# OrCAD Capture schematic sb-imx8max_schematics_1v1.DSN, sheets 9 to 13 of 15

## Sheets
9 02. B2B CONNECTOR: size C; title: 02. B2B CONNECTOR; note: 8000064001
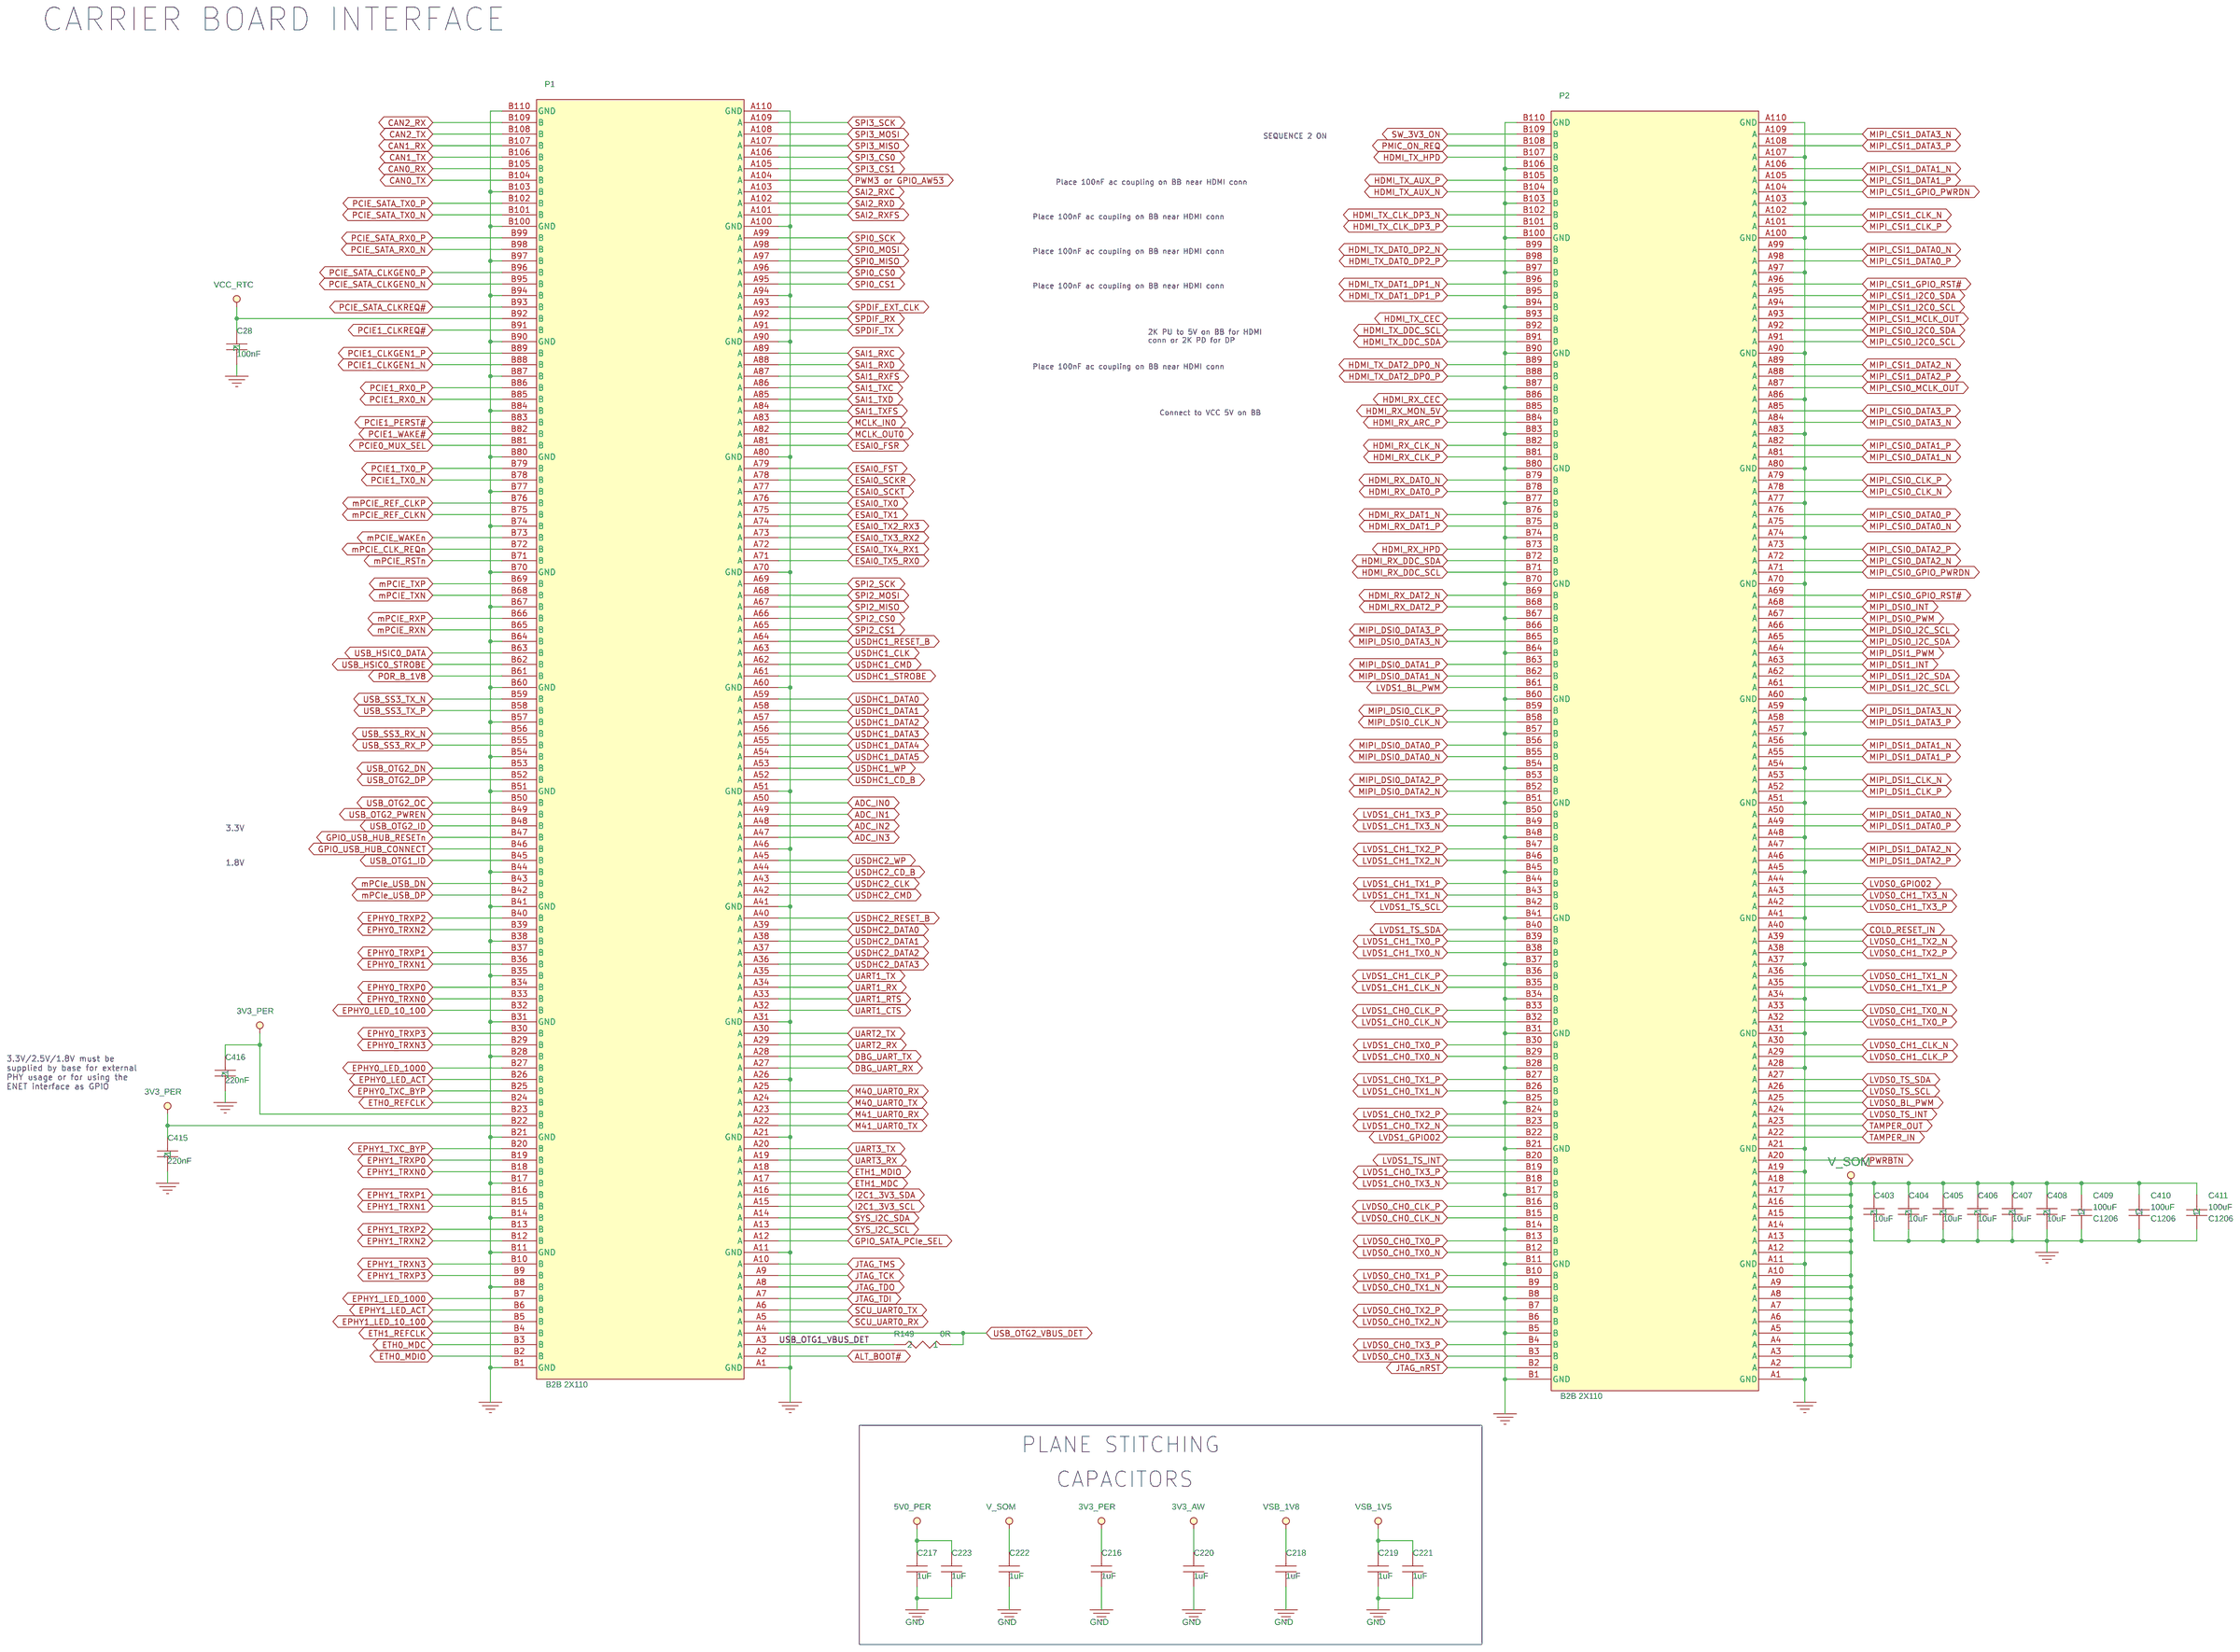
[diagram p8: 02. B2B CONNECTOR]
10 03. ETHERNET 0 , 1: size B; title: 03. ETHERNET 1 , 2; note: 8000064001
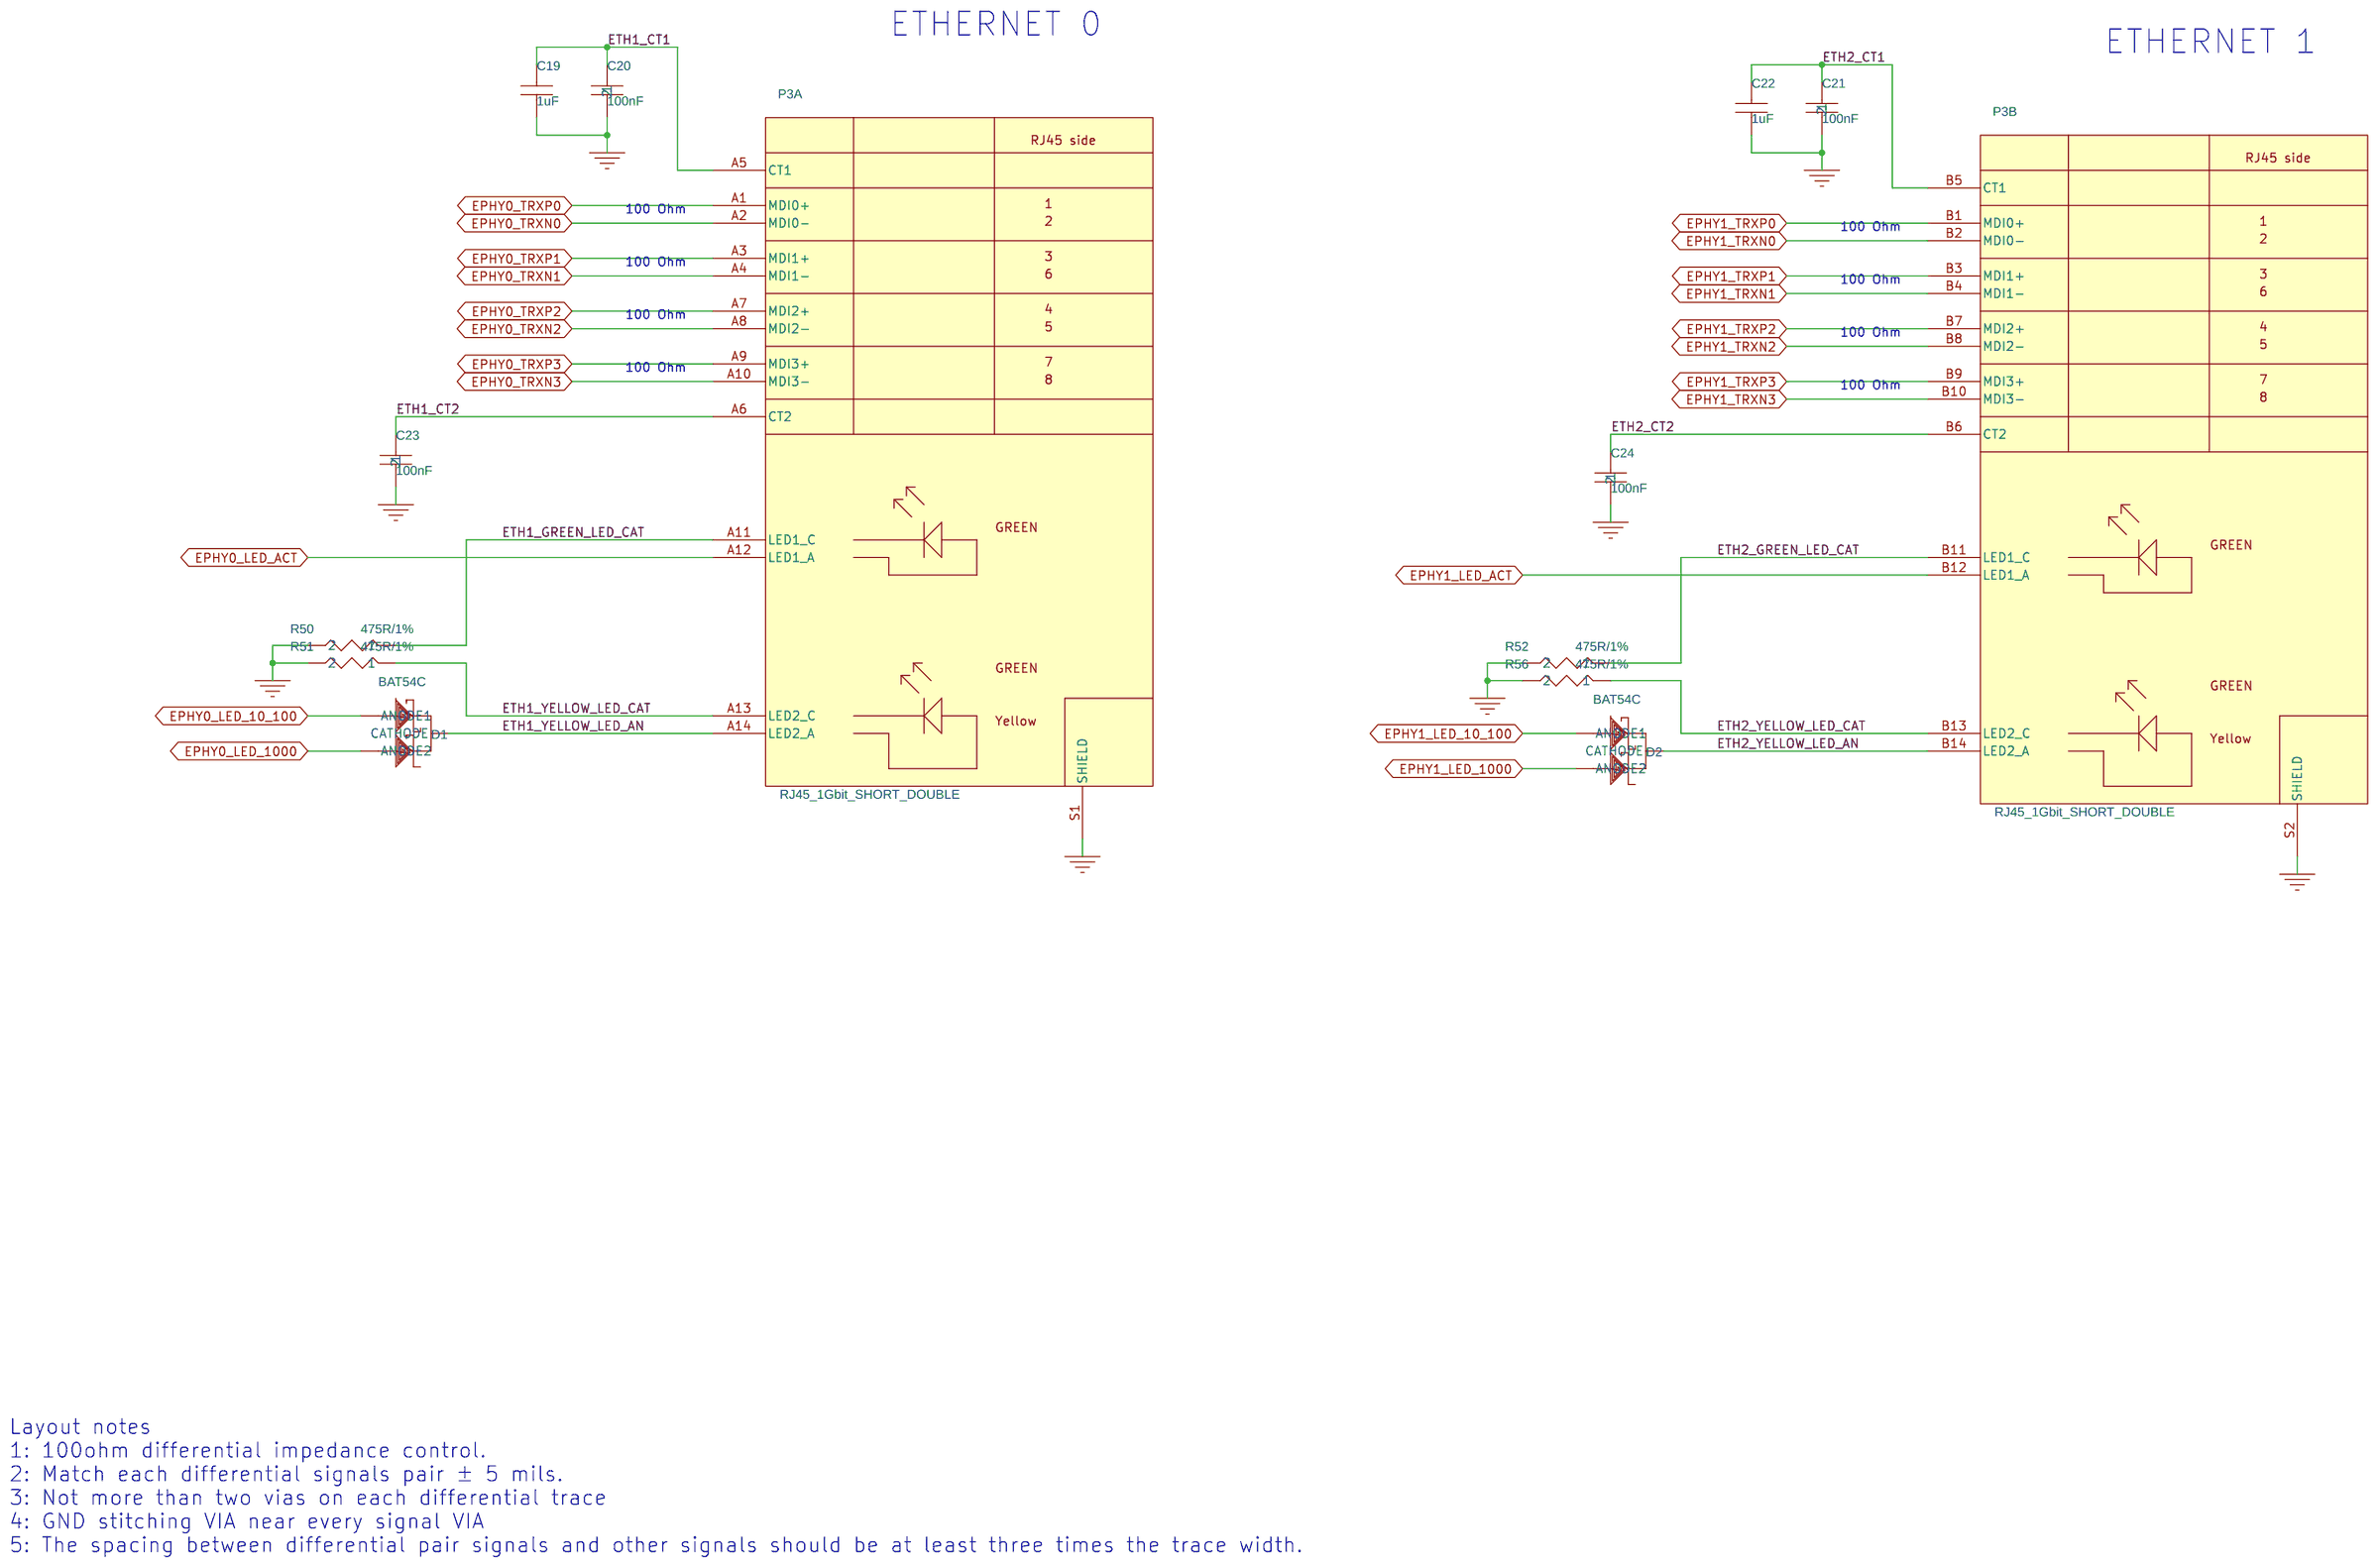
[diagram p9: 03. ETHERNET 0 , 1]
11 04. USB: size C; title: 04. USB; note: 8010055003
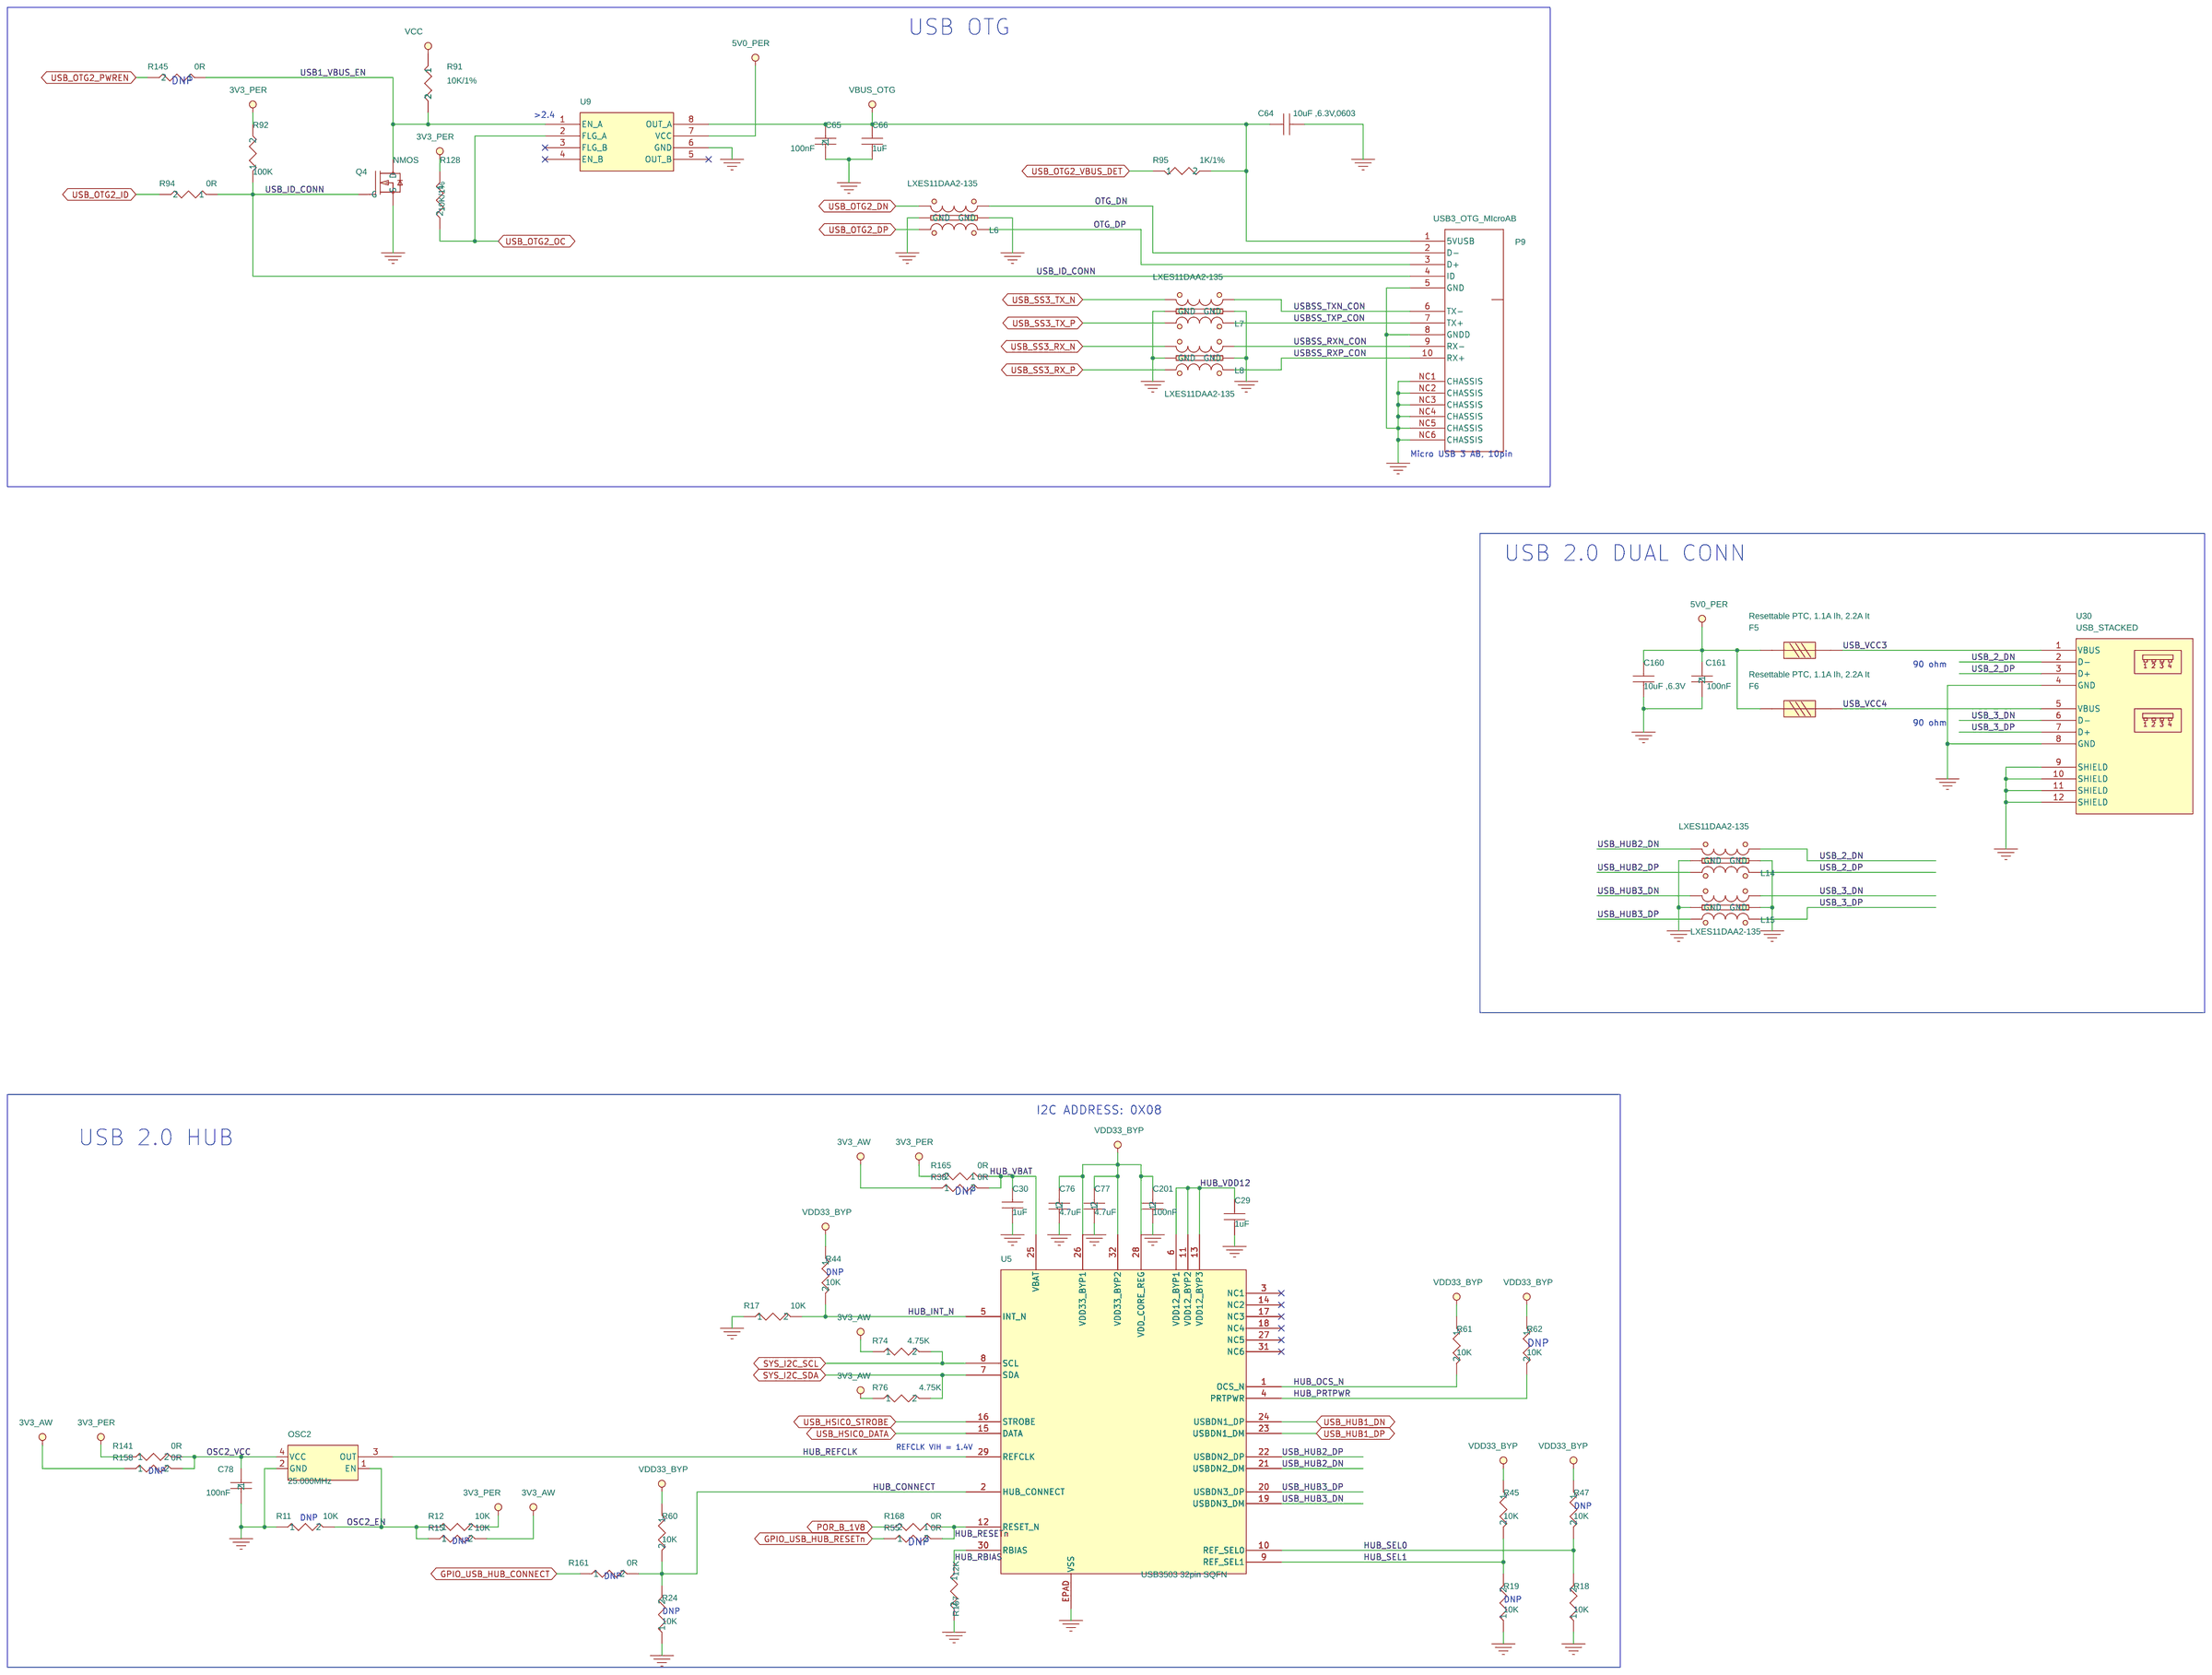
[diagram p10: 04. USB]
12 06. JTAG, 100 MIL CONN: size B; title: 06. 100 MIL CONN; note: 8010055003
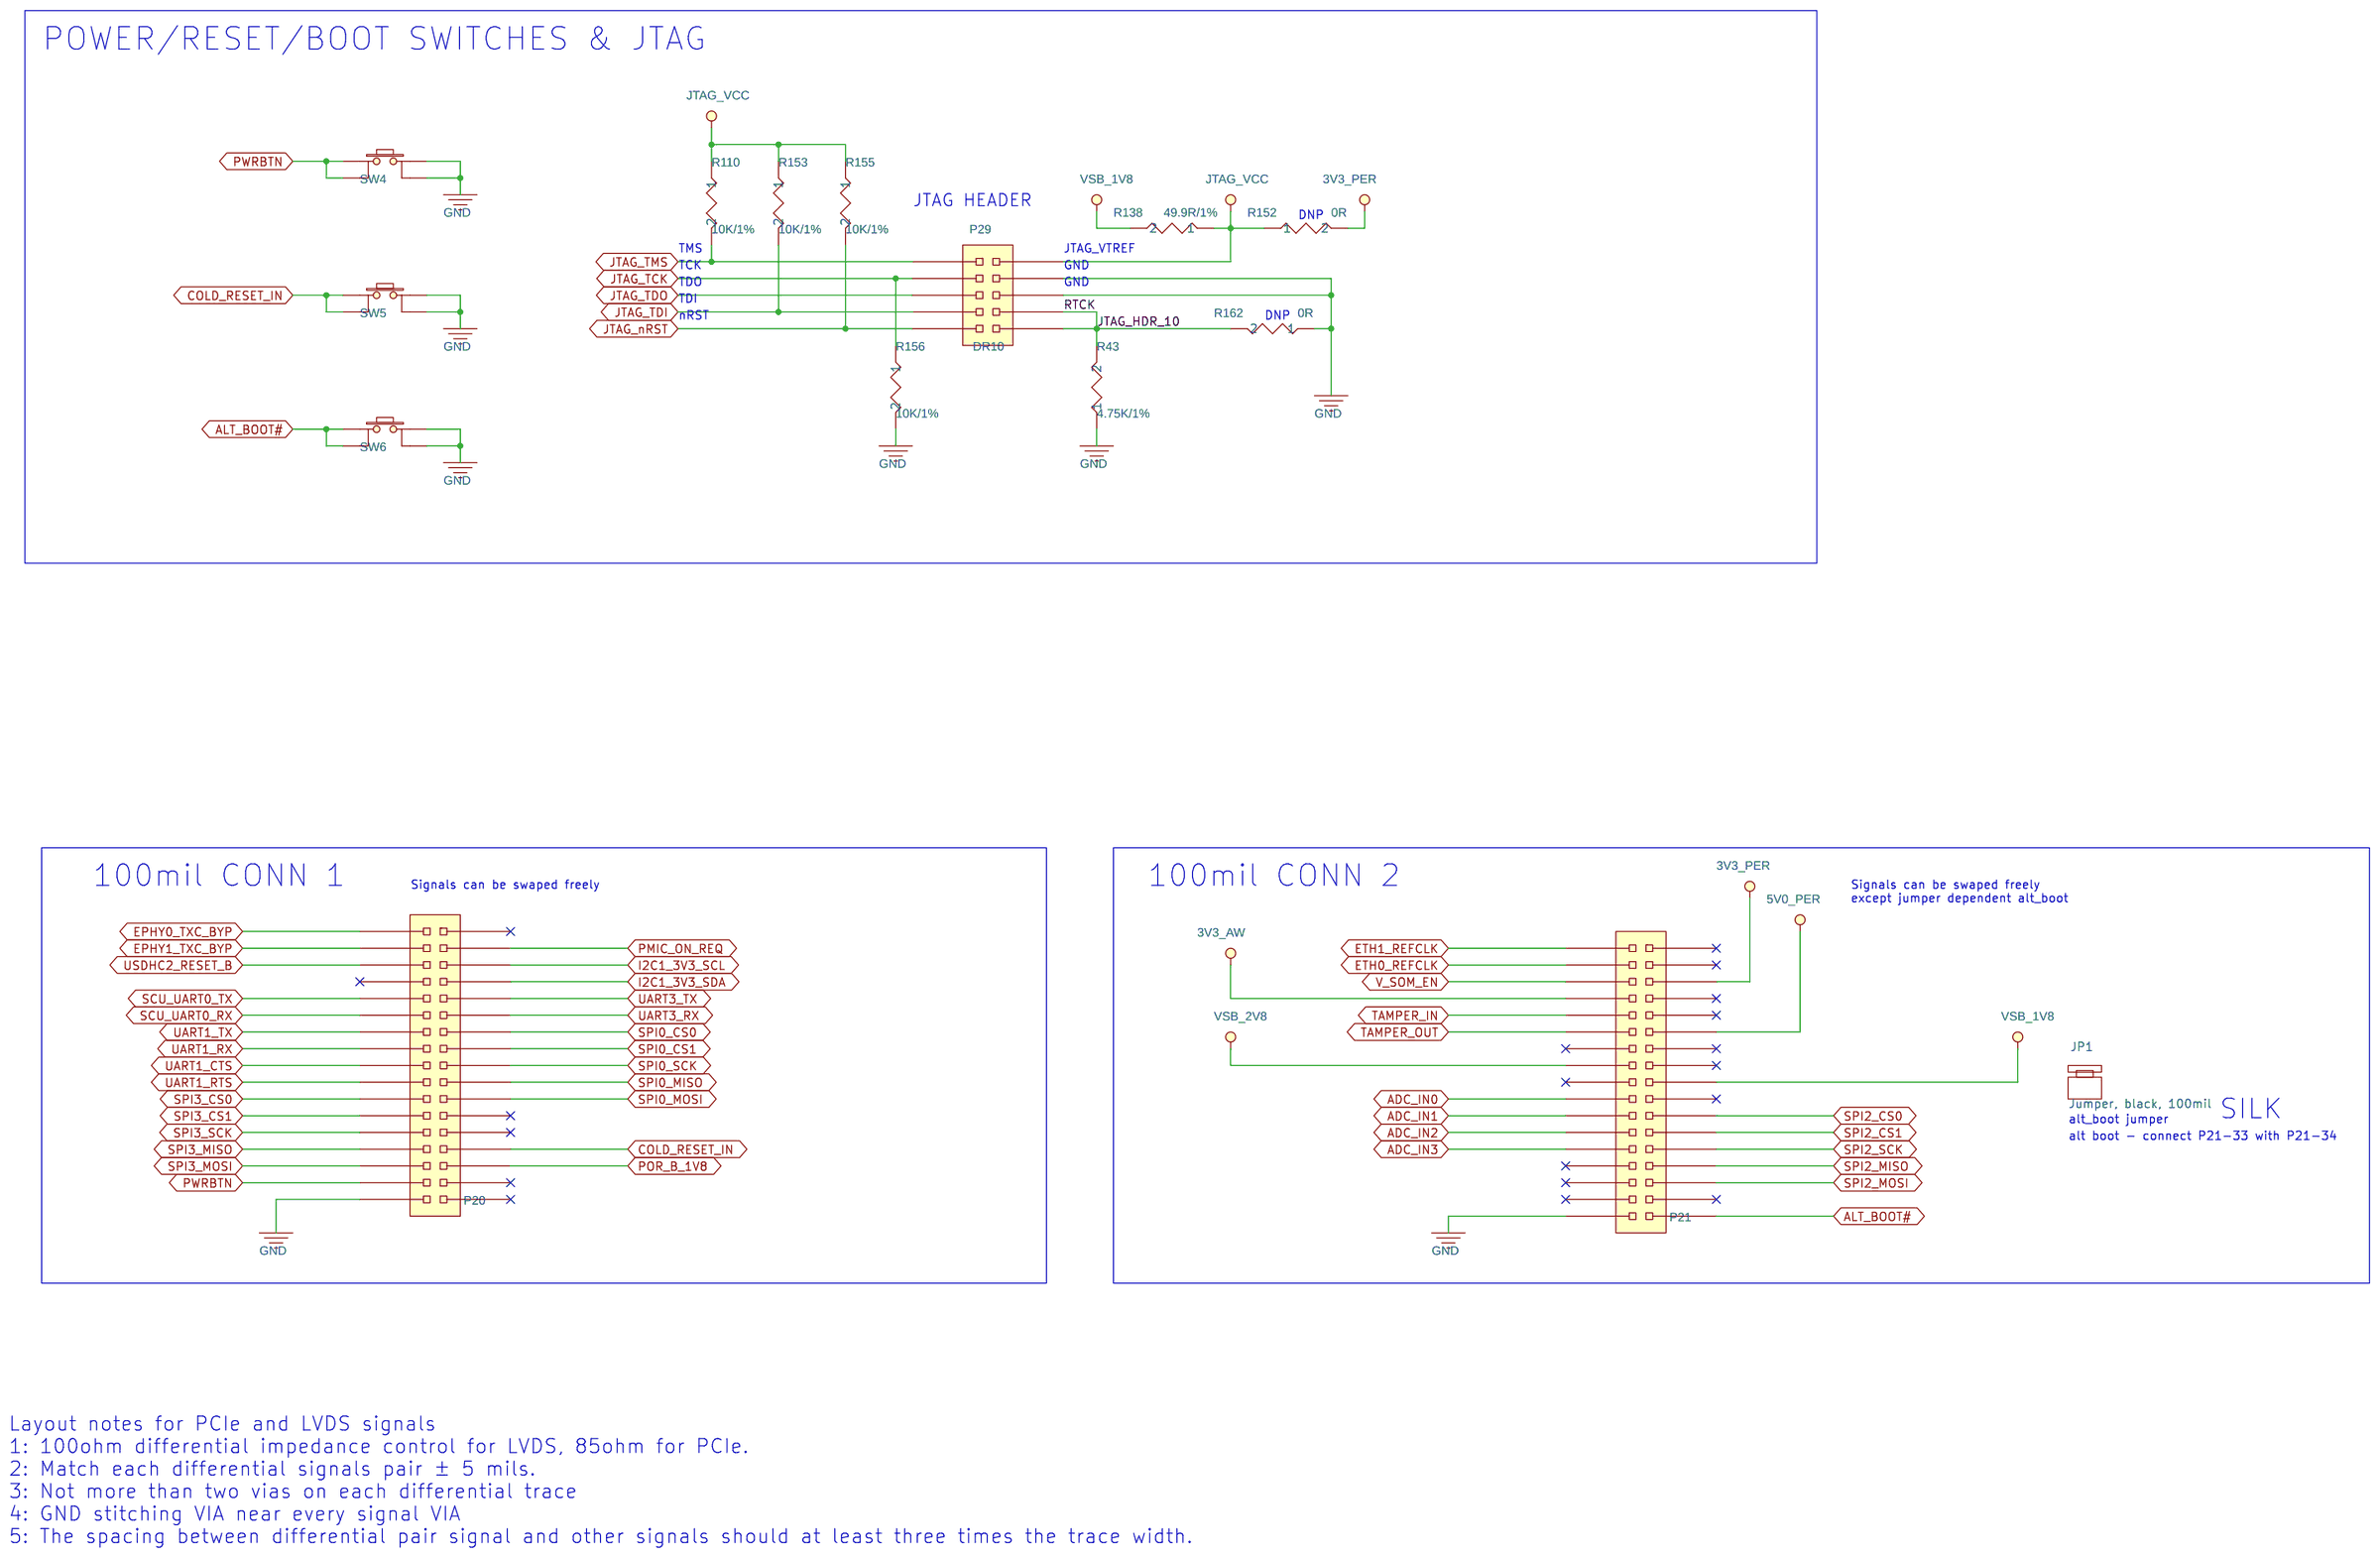
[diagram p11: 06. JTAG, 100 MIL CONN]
13 07. CSI, CAN, GPIO EXP: size C; title: 07. CSI, CAN,GPIO EXP; note: 8010055003
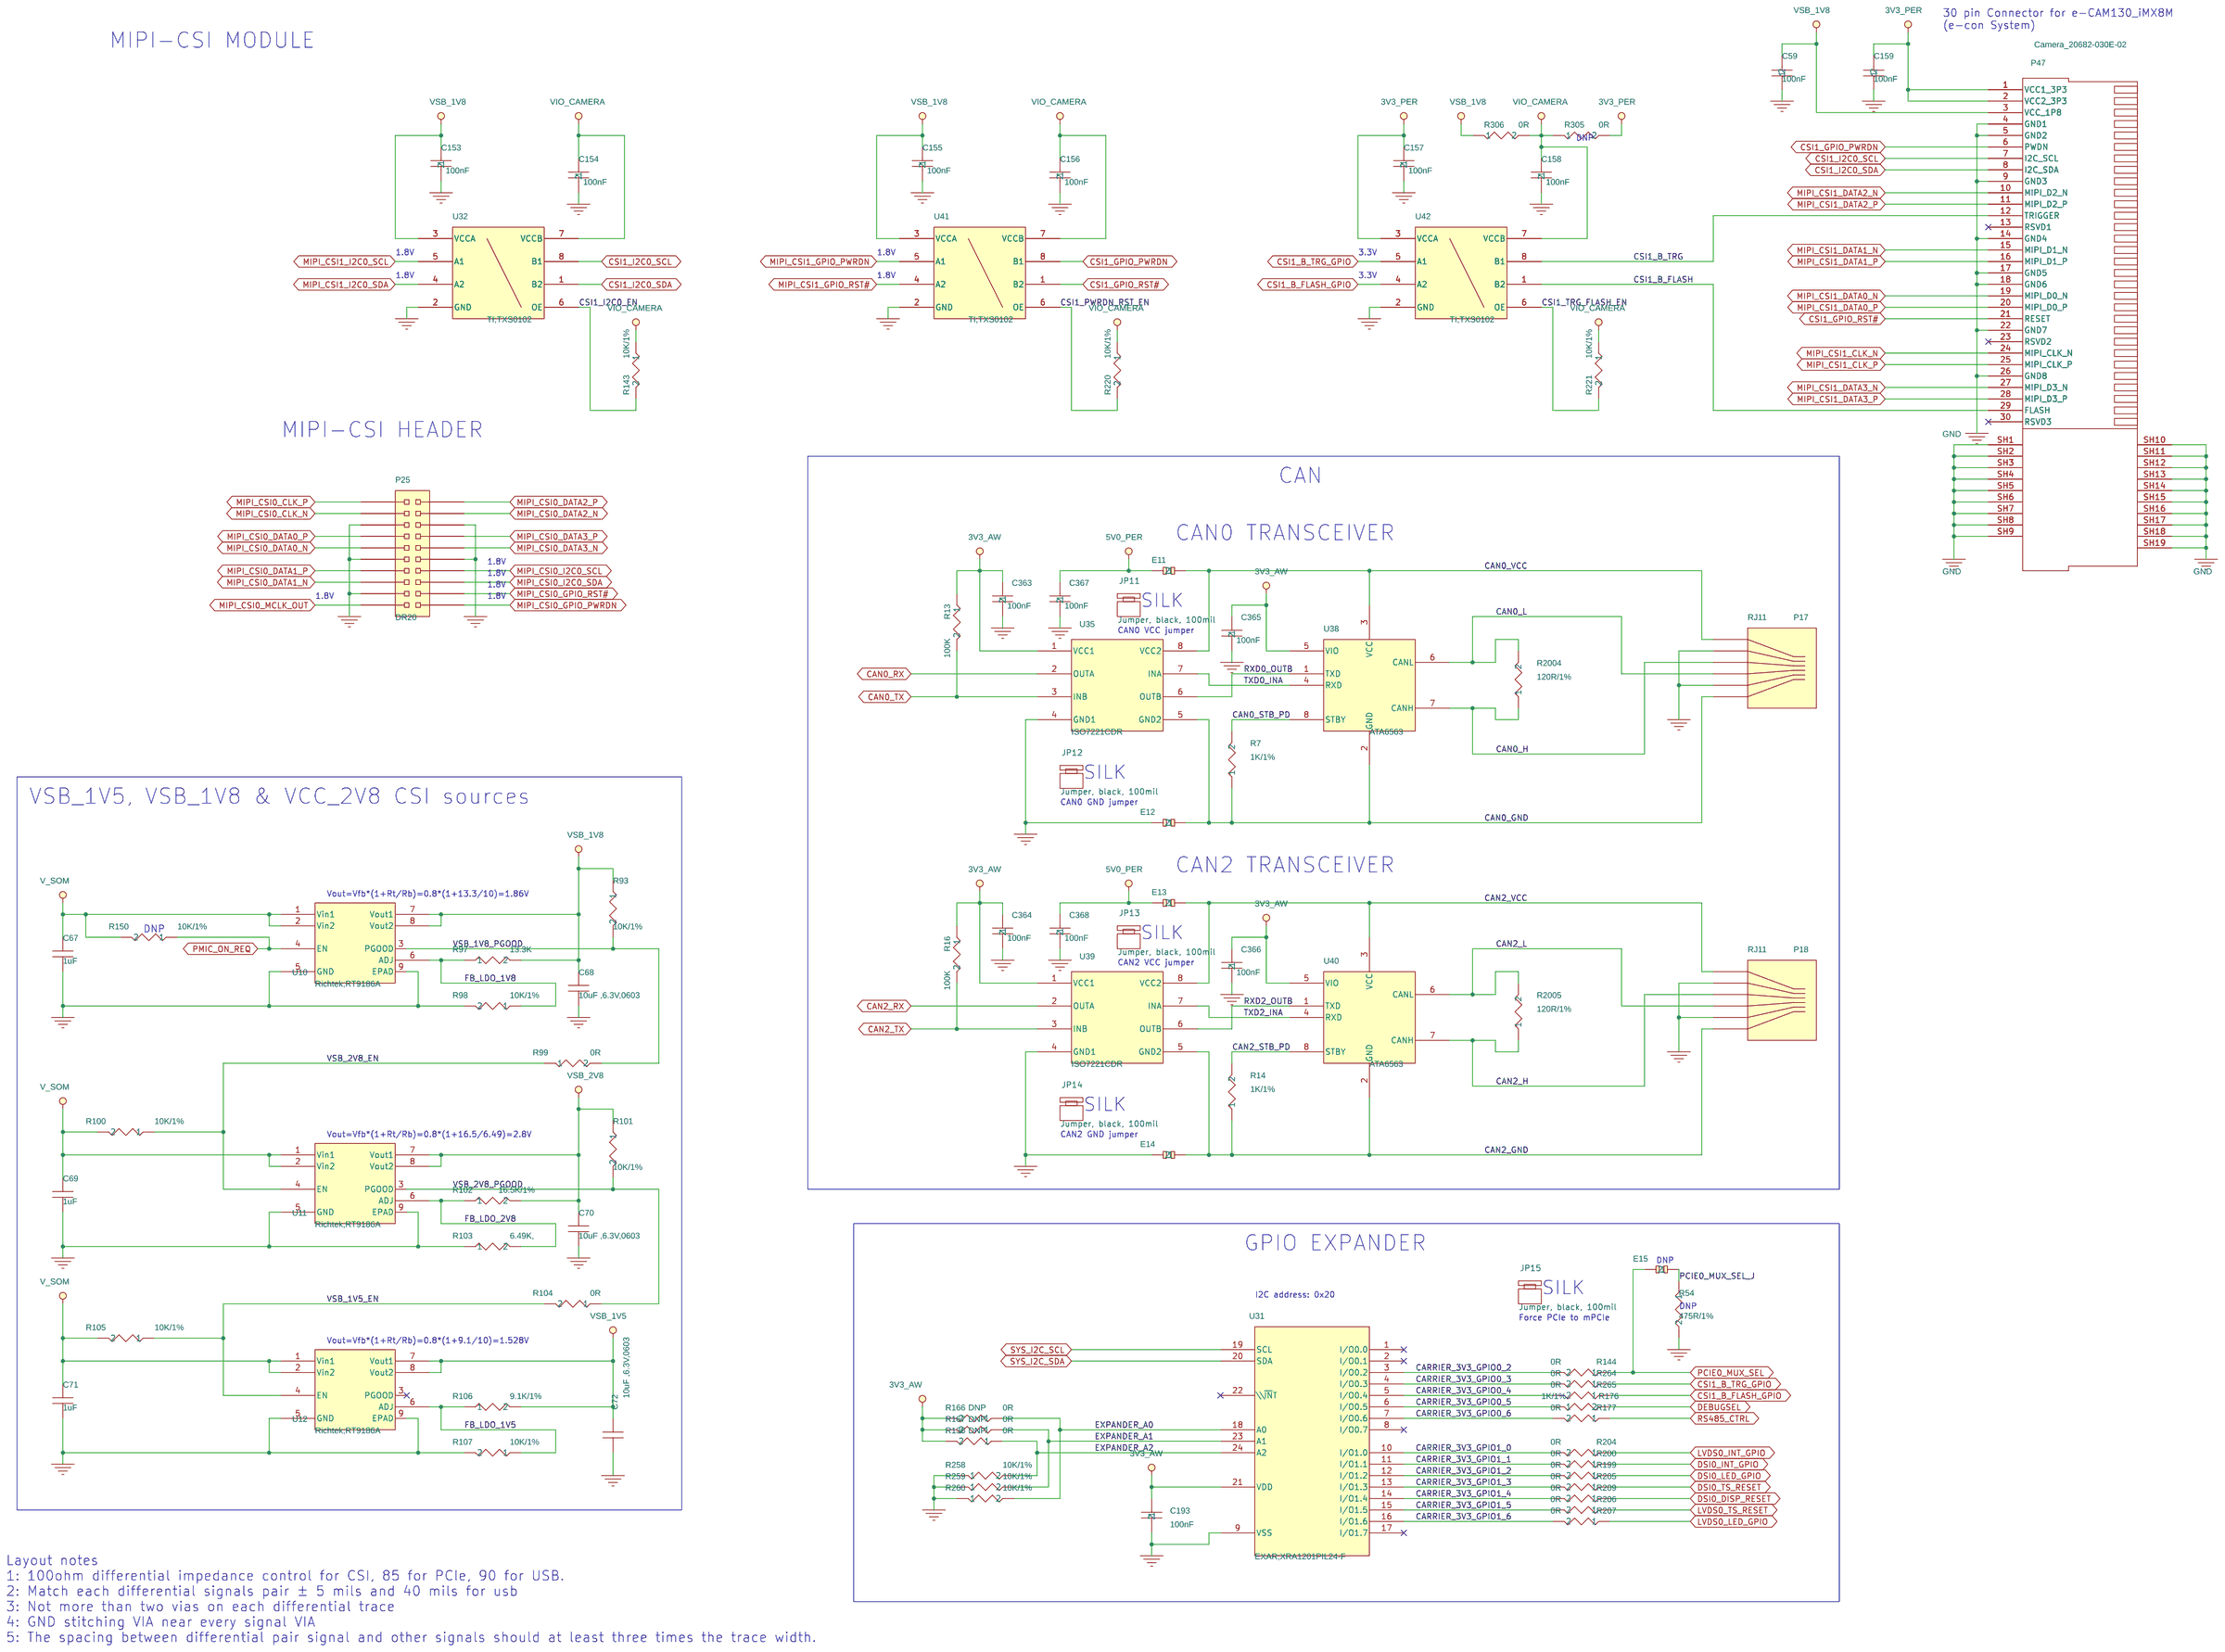
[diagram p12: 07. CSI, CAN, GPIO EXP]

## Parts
sheet 02. B2B CONNECTOR
C28  100nF  [RC0402]
C216  1uF  [RC0402]
C217  1uF  [RC0402]
C218  1uF  [RC0402]
C219  1uF  [RC0402]
C220  1uF  [RC0402]
C221  1uF  [RC0402]
C222  1uF  [RC0402]
C223  1uF  [RC0402]
C403  10uF  [RC0402]
C404  10uF  [RC0402]
C405  10uF  [RC0402]
C406  10uF  [RC0402]
C407  10uF  [RC0402]
C408  10uF  [RC0402]
C409  100uF  [C1206]
C410  100uF  [C1206]
C411  100uF  [C1206]
C415  220nF  [RC0402]
C416  220nF  [RC0402]
P1  B2B 2X110
P2  B2B 2X110
R149  0R  [RC0402]
sheet 03. ETHERNET 0 , 1
C19  1uF  [RC0402]
C20  100nF  [RC0402]
C21  100nF  [RC0402]
C22  1uF  [RC0402]
C23  100nF  [RC0402]
C24  100nF  [RC0402]
D1  BAT54C  [SOT23]
D2  BAT54C  [SOT23]
P3  RJ45_1Gbit_SHORT_DOUBLE  [RJTR1GRATHX2]  (sections A,B)
R50  475R/1%  [RC0402]
R51  475R/1%  [RC0402]
R52  475R/1%  [RC0402]
R56  475R/1%  [RC0402]
sheet 04. USB
C29  1uF  [RC0402]
C30  1uF  [RC0402]
C64  10uF ,6.3V,0603  [C0603-08]
C65  100nF  [RC0402]
C66  1uF  [RC0402]
C76  4.7uF  [RC0402]
C77  4.7uF  [RC0402]
C78  100nF  [RC0402]
C160  10uF ,6.3V  [C0603-08]
C161  100nF  [RC0402]
C201  100nF  [RC0402]
F5  Resettable PTC, 1.1A Ih, 2.2A It  [FUSE-1206]
F6  Resettable PTC, 1.1A Ih, 2.2A It  [FUSE-1206]
L6  LXES11DAA2-135  [EMI1012-ESD]
L7  LXES11DAA2-135  [EMI1012-ESD]
L8  LXES11DAA2-135  [EMI1012-ESD]
L14  LXES11DAA2-135  [EMI1012-ESD]
L15  LXES11DAA2-135  [EMI1012-ESD]
OSC2  25.000MHz  [OSC3225]
P9  USB3_OTG_MIcroAB  [MICRO-USB3-AB-RA-SM]
Q4  NMOS  [SOT23]
R11  10K  [RC0402]
R12  10K  [RC0402]
R15  10K  [RC0402]
R17  10K  [RC0402]
R18  10K  [RC0402]
R19  10K  [RC0402]
R24  10K  [RC0402]
R38  0R  [RC0402]
R44  10K  [RC0402]
R45  10K  [RC0402]
R47  10K  [RC0402]
R55  0R  [RC0402]
R60  10K  [RC0402]
R61  10K  [RC0402]
R62  10K  [RC0402]
R74  4.75K  [RC0402]
R76  4.75K  [RC0402]
R91  10K/1%  [RC0402]
R92  100K  [RC0402]
R94  0R  [RC0402]
R95  1K/1%  [RC0402]
R128  10K/1%  [RC0402]
R141  0R  [RC0402]
R145  0R  [RC0402]
R157  12K  [RC0402]
R158  0R  [RC0402]
R161  0R  [RC0402]
R165  0R  [RC0402]
R168  0R  [RC0402]
U5  USB3503 32pin SQFN
U9  AIC;AIC1528-1GSTR  [SO-8-150]
U30  USB_STACKED  [USB-2XA-TH]
sheet 06. JTAG, 100 MIL CONN
JP1  Jumper, black, 100mil
P20  Jih_Vei_Electronics;21N22564-34M10B-01G-6/1.5 –C  [2X17SMHDR]
P21  Jih_Vei_Electronics;21N22564-34M10B-01G-6/1.5 –C  [2X17SMHDR]
P29  DR10  [2X5THHDR]
R43  4.75K/1%  [RC0402]
R110  10K/1%  [RC0402]
R138  49.9R/1%  [RC0402]
R152  0R  [RC0402]
R153  10K/1%  [RC0402]
R155  10K/1%  [RC0402]
R156  10K/1%  [RC0402]
R162  0R  [RC0402]
SW4  PushB  [TACTSW6x6SM]
SW5  PushB  [TACTSW6x6SM]
SW6  PushB  [TACTSW6x6SM]
sheet 07. CSI, CAN, GPIO EXP
C59  100nF  [RC0402]
C67  1uF  [RC0402]
C68  10uF ,6.3V,0603  [C0603-08]
C69  1uF  [RC0402]
C70  10uF ,6.3V,0603  [C0603-08]
C71  1uF  [RC0402]
C72  10uF ,6.3V,0603  [C0603-08]
C153  100nF  [RC0402]
C154  100nF  [RC0402]
C155  100nF  [RC0402]
C156  100nF  [RC0402]
C157  100nF  [RC0402]
C158  100nF  [RC0402]
C159  100nF  [RC0402]
C193  100nF  [RC0402]
C363  100nF  [RC0402]
C364  100nF  [RC0402]
C365  100nF  [RC0402]
C366  100nF  [RC0402]
C367  100nF  [RC0402]
C368  100nF  [RC0402]
E11  HDR1X2  [1X2THHDR]
E12  HDR1X2  [1X2THHDR]
E13  HDR1X2  [1X2THHDR]
E14  HDR1X2  [1X2THHDR]
E15  HDR1X2  [1X2THHDR]
JP11  Jumper, black, 100mil
JP12  Jumper, black, 100mil
JP13  Jumper, black, 100mil
JP14  Jumper, black, 100mil
JP15  Jumper, black, 100mil
P17  RJ11  [RJ11TH6-6]
P18  RJ11  [RJ11TH6-6]
P25  DR20  [2X12THHDR]
P47  Camera_20682-030E-02  [CON30]
R7  1K/1%  [RC0402]
R13  100K  [RC0402]
R14  1K/1%  [RC0402]
R16  100K  [RC0402]
R54  475R/1%  [RC0402]
R93  10K/1%  [RC0402]
R97  13.3K  [RC0402]
R98  10K/1%  [RC0402]
R99  0R  [RC0402]
R100  10K/1%  [RC0402]
R101  10K/1%  [RC0402]
R102  16.5K/1%  [RC0402]
R103  6.49K,  [RC0402]
R104  0R  [RC0402]
R105  10K/1%  [RC0402]
R106  9.1K/1%  [RC0402]
R107  10K/1%  [RC0402]
R136  0R  [RC0402]
R143  10K/1%  [RC0402]
R144  0R  [RC0402]
R150  10K/1%  [RC0402]
R166  0R  [RC0402]
R167  0R  [RC0402]
R176  1K/1%  [RC0402]
R177  0R  [RC0402]
R199  0R  [RC0402]
R200  0R  [RC0402]
R204  0R  [RC0402]
R205  0R  [RC0402]
R206  0R  [RC0402]
R207  0R  [RC0402]
R209  0R  [RC0402]
R220  10K/1%  [RC0402]
R221  10K/1%  [RC0402]
R258  10K/1%  [RC0402]
R259  10K/1%  [RC0402]
R260  10K/1%  [RC0402]
R264  0R  [RC0402]
R265  0R  [RC0402]
R305  0R  [RC0402]
R306  0R  [RC0402]
R2004  120R/1%  [RC0603]
R2005  120R/1%  [RC0603]
U10  Richtek;RT9186A  [DFN3x3-8]
U11  Richtek;RT9186A  [DFN3x3-8]
U12  Richtek;RT9186A  [DFN3x3-8]
U31  EXAR;XRA1201PIL24-F  [QFN4x4-24]
U32  TI;TXS0102  [MO-187DA-8]
U35  ISO7221CDR  [SO-8-150]
U38  ATA6563
U39  ISO7221CDR  [SO-8-150]
U40  ATA6563
U41  TI;TXS0102  [MO-187DA-8]
U42  TI;TXS0102  [MO-187DA-8]

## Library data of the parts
C28 = 100nF,_10V,_X7R,_10%,_0402_2: CLABCONF0: SB-iMX8MAX; P/N: 151B104B0S
C19 C22 C29 C30 C66 C67 C69 C71 C216-C223 = 1uF,X5R,6.3V,0402: CLABCONF0: SB-iMX8MAX
C403 = 10uF_10V_20%_0402_2: CLABCONF0: SB-iMX8MAX
C404 = 10uF_10V_20%_0402_1: CLABCONF0: SB-iMX8MAX
C405 = 10uF_10V_20%_0402_4: CLABCONF0: SB-iMX8MAX
C406 = 10uF_10V_20%_0402: CLABCONF0: SB-iMX8MAX
C407 = 10uF_10V_20%_0402_5: CLABCONF0: SB-iMX8MAX
C408 = 10uF_10V_20%_0402_3: CLABCONF0: SB-iMX8MAX
C409 = 100nF,_10V,_X7R,_10%,_0402: CLABCONF0: SB-iMX8MAX; P/N: 151B10730S
C410 = 100nF,_10V,_X7R,_10%,_0402_1: CLABCONF0: SB-iMX8MAX; P/N: 151B10730S
C411 = 100nF,_10V,_X7R,_10%,_0402_4: CLABCONF0: SB-iMX8MAX; P/N: 151B10730S
C415 = 100nF,_10V,_X7R,_10%,_0402_3: CLABCONF0: SB-iMX8MAX; P/N: 151C224B0S
C416 = 100nF,_10V,_X7R,_10%,_0402_5: CLABCONF0: SB-iMX8MAX; P/N: 151C224B0S
P1 P2 = B2B_2X110_1: CLABCONF0: SB-iMX8MAX; P/N: 182E22000S
R149 R165 R206 = 0R,_0402_1: CLABCONF0: SB-iMX8MAX
C20 = 100nF,_10V,_X7R,_10%,_0402_3: CLABCONF0: SB-iMX8MAX; Group: LAN2
C21 = 100nF,_10V,_X7R,_10%,_0402_2: CLABCONF0: SB-iMX8MAX; Group: LAN2
C23 = 100nF,_10V,_X7R,_10%,_0402: CLABCONF0: SB-iMX8MAX; Group: LAN2
C24 = 100nF,_10V,_X7R,_10%,_0402_1: CLABCONF0: SB-iMX8MAX; Group: LAN2
D1 D2 = BAT54C: CLABCONF0: SB-iMX8MAX
P3 = RJ45_1Gbit_SHORT_DOUBLE: CLABCONF0: SB-iMX8MAX; Color: Default; Location X-Coordinate: 0; Location Y-Coordinate: 0; P/N: 182K02800; Power Pins Visible: False; Primitive: DEFAULT
R50 = 475R_1%,_0402_1: CLABCONF0: SB-iMX8MAX
R51 = 475R_1%,_0402: CLABCONF0: SB-iMX8MAX
R52 = 475R_1%,_0402_3: CLABCONF0: SB-iMX8MAX
R56 = 475R_1%,_0402_2: CLABCONF0: SB-iMX8MAX
C64 C68 C70 C72 C160 = 10uF,6_0.3V,0603,20%X5R: CLABCONF0: SB-iMX8MAX
C59 C65 = 100nF,_10V,_X7R,_10%,_0402_1: CLABCONF0: SB-iMX8MAX
C76 = 15pF,_50V,_NPO,_5%,_0402: CLABCONF0: SB-iMX8MAX; P/N: 151B47500S
C77 = 15pF,_50V,_NPO,_5%,_0402_1: CLABCONF0: SB-iMX8MAX; P/N: 151B47500S
C78 C154 = 100nF,_10V,_X7R,_10%,_0402_3: CLABCONF0: SB-iMX8MAX
C153 C161 = 100nF,_10V,_X7R,_10%,_0402: CLABCONF0: SB-iMX8MAX
C201 = 100nF,_10V,_X7R,_10%,_0402_2: CLABCONF0: SB-iMX8MAX
F5 F6 = Fuse,_0.75A_Ih,_1.5A_It: CLABCONF0: SB-iMX8MAX; P/N: 175P22200S
L6-L8 L14 L15 = ESD_CHOKE_DIFFx2_10: CLABCONF0: SB-iMX8MAX; P/N: 142D11801S
OSC2 = Osc.,_50Mhz,50PPM,_3.3V: CLABCONF0: SB-iMX8MAX; P/N: 141C25601S
P9 = USB3_OTGMINIB_5: CLABCONF0: SB-iMX8MAX; P/N: 180K01000S
Q4 = N-MOSFET,NDS335N,100mOhm@2.5V: CLABCONF0: SB-iMX8MAX
R11 = 1M_,5%,_0402_1: CLABCONF0: DNP; P/N: 161C10021S
R12 = 1M_,5%,_0402_3: CLABCONF0: SB-iMX8MAX; P/N: 161C10021S
R15 = 1M_,5%,_0402_7: CLABCONF0: DNP; P/N: 161C10021S
R17 = 1M_,5%,_0402_8: CLABCONF0: SB-iMX8MAX; P/N: 161C10021S
R18 = 1M_,5%,_0402_5: CLABCONF0: SB-iMX8MAX; P/N: 161C10021S
R19 = 1M_,5%,_0402_6: CLABCONF0: DNP; P/N: 161C10021S
R24 = 1M_,5%,_0402_9: CLABCONF0: DNP; P/N: 161C10021S
R38 R162 = 0R,_0402_1: CLABCONF0: DNP
R44 = 1M_,5%,_0402_4: CLABCONF0: DNP; P/N: 161C10021S
R45 = 1M_,5%,_0402: CLABCONF0: SB-iMX8MAX; P/N: 161C10021S
R47 = 1M_,5%,_0402_2: CLABCONF0: DNP; P/N: 161C10021S
R55 R152 = 0R,_0402: CLABCONF0: DNP
R60 = 1M_,5%,_0402_11: CLABCONF0: SB-iMX8MAX; P/N: 161C10021S
R61 = 1M_,5%,_0402_10: CLABCONF0: SB-iMX8MAX; P/N: 161C10021S
R62 = 1M_,5%,_0402_12: CLABCONF0: DNP; P/N: 161C10021S
R74 = 4_0.75K,1%,0402,1_16W_1: CLABCONF0: SB-iMX8MAX
R43 R76 = 4_0.75K,1%,0402,1_16W: CLABCONF0: SB-iMX8MAX
R91 R153 R260 = 10K,1%,0402,1_16W: CLABCONF0: SB-iMX8MAX
R13 R92 = 100K,_0402: CLABCONF0: SB-iMX8MAX; P/N: 161C10031S
R94 R207 = 0R,_0402_1_2: CLABCONF0: SB-iMX8MAX
R95 R176 = 1K,1%,0402,1_16W: CLABCONF0: SB-iMX8MAX; Group: CAN
R128 R155 = 10K,1%,0402,1_16W_1: CLABCONF0: SB-iMX8MAX
R99 R141 = 0R,_0402_1_3: CLABCONF0: SB-iMX8MAX
R145 = 0R,_0402_1_5: CLABCONF0: DNP
R157 = 4.99K,1%,0402,1_16W: CLABCONF0: SB-iMX8MAX; P/N: 161C12021S
R158 R167 = 0R,_0402_1_4: CLABCONF0: DNP
R161 R166 = 0R,_0402_1_1: CLABCONF0: DNP
R144 R168 = 0R,_0402_1_6: CLABCONF0: SB-iMX8MAX
U5 = USB3503_32-pin_0: CLABCONF0: SB-iMX8MAX; P/N: 116A35031S
U9 = RYC8220-1M_DUAL_USB_PWR_SWITCH: CLABCONF0: SB-iMX8MAX
U30 = USB_A-TYPE_DOUBLE_TH: CLABCONF0: SB-iMX8MAX; Group: Front Panel
JP1 JP11-JP15 = Jumper,_black,_100mil: CLABCONF0: SB-iMX8MAX
P20 P21 = HDR_2x17_100MIL_SMT: CLABCONF0: SB-iMX8MAX
P29 = HDR_2x5_100MIL_TH: CLABCONF0: SB-iMX8MAX; Group: COM2
R93 R110 = 10K,1%,0402,1_16W_3: CLABCONF0: SB-iMX8MAX
R138 = 49.9R_1%,_0402: CLABCONF0: SB-iMX8MAX
R156 R221 = 10K,1%,0402,1_16W_2: CLABCONF0: SB-iMX8MAX
SW4-SW6 = TACT_SW_6x6mm_SMT: CLABCONF0: SB-iMX8MAX
C155 = 100nF,_10V,_X7R,_10%,_0402_4: CLABCONF0: SB-iMX8MAX
C156 = 100nF,_10V,_X7R,_10%,_0402_12: CLABCONF0: SB-iMX8MAX
C157 = 100nF,_10V,_X7R,_10%,_0402_10: CLABCONF0: SB-iMX8MAX
C158 = 100nF,_10V,_X7R,_10%,_0402_13: CLABCONF0: SB-iMX8MAX
C159 = 100nF,_10V,_X7R,_10%,_0402_7: CLABCONF0: SB-iMX8MAX
C193 = 100nF,_10V,_X7R,_10%,_0402_6: CLABCONF0: SB-iMX8MAX
C363 = 100nF,_10V,_X7R,_10%,_0402_2: CLABCONF0: SB-iMX8MAX; Group: CAN
C364 = 100nF,_10V,_X7R,_10%,_0402_9: CLABCONF0: SB-iMX8MAX; Group: CAN
C365 = 100nF,_10V,_X7R,_10%,_0402_5: CLABCONF0: SB-iMX8MAX; Group: CAN
C366 = 100nF,_10V,_X7R,_10%,_0402_8: CLABCONF0: SB-iMX8MAX; Group: CAN
C367 = 100nF,_10V,_X7R,_10%,_0402_11: CLABCONF0: SB-iMX8MAX; Group: CAN
C368 = 100nF,_10V,_X7R,_10%,_0402_14: CLABCONF0: SB-iMX8MAX; Group: CAN
E11 = HDR_1x2_100MIL_TH_JUMPER_3: CLABCONF0: SB-iMX8MAX
E12 = HDR_1x2_100MIL_TH_JUMPER: CLABCONF0: SB-iMX8MAX
E13 = HDR_1x2_100MIL_TH_JUMPER_4: CLABCONF0: SB-iMX8MAX
E14 = HDR_1x2_100MIL_TH_JUMPER_1: CLABCONF0: SB-iMX8MAX
E15 = HDR_1x2_100MIL_TH_JUMPER_2: CLABCONF0: DNP
P17 P18 = RJ11: CLABCONF0: SB-iMX8MAX
P25 = HDR_2x12_100MIL_0: CLABCONF0: SB-iMX8MAX; P/N: 190C02000S
P47 = Camera_20682-030E-02: CLABCONF0: SB-iMX8MAX; P/N: 182K03002S
R7 = 1K,1%,0402,1_16W_1: CLABCONF0: SB-iMX8MAX; Group: CAN
R14 = 1K,1%,0402,1_16W_2: CLABCONF0: SB-iMX8MAX; Group: CAN
R16 = 100K,_0402_1: CLABCONF0: SB-iMX8MAX; P/N: 161C10031S
R54 = 475R_1%,_0402: CLABCONF0: DNP
R97 = 13.3K,_0402_tmp: CLABCONF0: SB-iMX8MAX; P/N: 161C13321S
R98 = 10K,1%,0402,1_16W_5: CLABCONF0: SB-iMX8MAX
R100 = 10K,1%,0402,1_16W_7: CLABCONF0: SB-iMX8MAX
R101 = 10K,1%,0402,1_16W_6: CLABCONF0: SB-iMX8MAX
R102 = 10K,1%,0402,1_16W_1: CLABCONF0: SB-iMX8MAX; P/N: 161C16521S
R103 = 33R,5%,0402,1_16W: CLABCONF0: SB-iMX8MAX; P/N: 161C64911S
R104 = 0R,_0402_1_7: CLABCONF0: SB-iMX8MAX
R105 = 10K,1%,0402,1_16W_10: CLABCONF0: SB-iMX8MAX
R106 = 953R,1%,0402,1_16W_0: CLABCONF0: SB-iMX8MAX; P/N: 161C91011S
R107 = 10K,1%,0402,1_16W_8: CLABCONF0: SB-iMX8MAX
R136 = 0R,_0402_1_11: CLABCONF0: DNP
R143 = 10K,1%,0402,1_16W_9: CLABCONF0: SB-iMX8MAX
R150 = 10K,1%,0402,1_16W_4: CLABCONF0: DNP
R177 = 0R,_0402_1_13: CLABCONF0: SB-iMX8MAX
R199 = 0R,_0402_1_10: CLABCONF0: SB-iMX8MAX
R200 = 0R,_0402_1_9: CLABCONF0: SB-iMX8MAX
R204 = 0R,_0402_1_8: CLABCONF0: SB-iMX8MAX
R205 = 0R,_0402_1_12: CLABCONF0: SB-iMX8MAX
R209 = 0R,_0402_1_15: CLABCONF0: SB-iMX8MAX
R220 = 10K,1%,0402,1_16W_13: CLABCONF0: SB-iMX8MAX
R258 = 10K,1%,0402,1_16W_11: CLABCONF0: SB-iMX8MAX
R259 = 10K,1%,0402,1_16W_12: CLABCONF0: SB-iMX8MAX
R264 = 0R,_0402_1_14: CLABCONF0: SB-iMX8MAX
R265 = 0R,_0402_1_5: CLABCONF0: SB-iMX8MAX
R305 = 0R,_0402_0: CLABCONF0: DNP; P/N: 161C00005S
R306 = 0R,_0402_0_1: CLABCONF0: SB-iMX8MAX; P/N: 161C00005S
R2004 = 120R_1%,_0603_1: CLABCONF0: SB-iMX8MAX
R2005 = 120R_1%,_0603: CLABCONF0: SB-iMX8MAX
U10-U12 = RT9186A,LDO_,2.5-5_0.5V,500mA: CLABCONF0: SB-iMX8MAX
U31 = PCA9555: CLABCONF0: SB-iMX8MAX
U32 U41 U42 = TXS0102_0: CLABCONF0: SB-iMX8MAX; P/N: 116A01020S
U35 U39 = AduM1201: CLABCONF0: SB-iMX8MAX; Group: CAN; P/N: 116A00390S
U38 U40 = ATA6563: CLABCONF0: SB-iMX8MAX; P/N: 116A00380S

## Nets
3V3_AW: C193.1 C220.1 C363.1 C364.1 C365.1 C366.1 P21.7 R13.1 R15.2 R16.1 R38.1 R74.1 R76.1 R136.2 R158.1 R166.2 R167.2 U31.21(VDD) U35.1(VCC1) U38.5(VIO) U39.1(VCC1) U40.5(VIO) ; also on sheet 5 14 15
3V3_PER: C157.1 C159.2 C216.1 C415.1 C416.1 P1.B22(B) P1.B23(B) P21.6 P47.1(VCC1_3P3) P47.2(VCC2_3P3) R12.2 R91.1 R92.2 R128.1 R141.1 R152.2 R165.2 R305.2 U42.3(VCCA) ; also on sheet 1 2 3 4 5 6 14 15
5V0_PER: C160.1 C161.1 C217.1 C223.1 C367.1 C368.1 E11.2 E13.2 F5.2 F6.2 P21.12 U9.7(VCC) ; also on sheet 1 4 15
GND: C19.2 C20.2 C21.2 C22.2 C23.2 C24.2 C28.2 C29.2 C30.2 C59.1 C64.2 C65.2 C66.2 C67.2 C68.2 C69.2 C70.2 C71.2 C72.2 C76.1 C77.1 C78.2 C153.2 C154.2 C155.2 C156.2 C157.2 C158.2 C159.1 C160.2 C161.2 C193.2 C201.1 C216.2 C217.2 C218.2 C219.2 C220.2 C221.2 C222.2 C223.2 C363.2 C364.2 C365.2 C366.2 C367.2 C368.2 C403.2 C404.2 C405.2 C406.2 C407.2 C408.2 C409.1 C410.1 C411.1 C415.2 C416.2 E12.2 E14.2 L6.5(GND) L6.6(GND) L7.5(GND) L7.6(GND) L8.5(GND) L8.6(GND) L14.5(GND) L14.6(GND) L15.5(GND) L15.6(GND) OSC2.2(GND) P1.A1(GND) P1.A11(GND) P1.A21(GND) P1.A26(A) P1.A31(GND) P1.A41(GND) P1.A46(A) P1.A51(GND) P1.A60(GND) P1.A70(GND) P1.A80(GND) P1.A90(GND) P1.A94(A) P1.A100(GND) P1.A110(GND) P1.B1(GND) P1.B8(B) P1.B11(GND) P1.B14(B) P1.B17(B) P1.B21(GND) P1.B28(B) P1.B31(GND) P1.B35(B) P1.B38(B) P1.B41(GND) P1.B44(B) P1.B51(GND) P1.B54(B) P1.B57(B) P1.B60(GND) P1.B64(B) P1.B67(B) P1.B70(GND) P1.B74(B) P1.B77(B) P1.B80(GND) P1.B84(B) P1.B87(B) P1.B90(GND) P1.B94(B) P1.B97(B) P1.B100(GND) P1.B103(B) P1.B110(GND) P2.A1(GND) P2.A11(GND) P2.A19(A) P2.A21(GND) P2.A28(A) P2.A31(GND) P2.A34(A) P2.A37(A) P2.A41(GND) P2.A45(A) P2.A48(A) P2.A51(GND) P2.A54(A) P2.A57(A) P2.A60(GND) P2.A70(GND) P2.A74(A) P2.A77(A) P2.A80(GND) P2.A83(A) P2.A86(A) P2.A90(GND) P2.A97(A) P2.A100(GND) P2.A103(A) P2.A107(A) P2.A110(GND) P2.B1(GND) P2.B5(B) P2.B8(B) P2.B11(GND) P2.B14(B) P2.B17(B) P2.B21(GND) P2.B25(B) P2.B28(B) P2.B31(GND) P2.B34(B) P2.B37(B) P2.B41(GND) P2.B45(B) P2.B48(B) P2.B51(GND) P2.B54(B) P2.B57(B) P2.B60(GND) P2.B64(B) P2.B67(B) P2.B70(GND) P2.B74(B) P2.B77(B) P2.B80(GND) P2.B83(B) P2.B87(B) P2.B90(GND) P2.B94(B) P2.B97(B) P2.B100(GND) P2.B103(B) P2.B106(B) P2.B110(GND) P3.S1(SHIELD) P3.S2(SHIELD) P9.5(GND) P9.8(GNDD) P9.NC1(CHASSIS) P9.NC2(CHASSIS) P9.NC3(CHASSIS) P9.NC4(CHASSIS) P9.NC5(CHASSIS) P9.NC6(CHASSIS) P17.2 P17.5 P18.2 P18.5 P20.33 P21.33 P25.5 P25.6 P25.11 P25.12 P25.17 P29.3 P29.5 P47.4(GND1) P47.5(GND2) P47.9(GND3) P47.14(GND4) P47.17(GND5) P47.18(GND6) P47.22(GND7) P47.26(GND8) P47.SH1 P47.SH2 P47.SH3 P47.SH4 P47.SH5 P47.SH6 P47.SH7 P47.SH8 P47.SH9 P47.SH10 P47.SH11 P47.SH12 P47.SH13 P47.SH14 P47.SH15 P47.SH16 P47.SH17 P47.SH18 P47.SH19 Q4.2(S) R11.1 R17.1 R18.1 R19.1 R24.1 R43.1 R50.2 R51.2 R52.2 R54.2 R56.2 R98.2 R103.1 R107.2 R156.2 R157.2 R162.1 R258.1 R259.1 R260.1 SW4.1 SW4.3 SW5.1 SW5.3 SW6.1 SW6.3 U5.EPAD(VSS) U9.6(GND) U10.5(GND) U10.9(EPAD) U11.5(GND) U11.9(EPAD) U12.5(GND) U12.9(EPAD) U30.4(GND) U30.8(GND) U30.9(SHIELD) U30.10(SHIELD) U30.11(SHIELD) U30.12(SHIELD) U31.9(VSS) U32.2(GND) U35.4(GND1) U39.4(GND1) U41.2(GND) U42.2(GND) ; also on sheet 1 2 3 4 5 6 7 14 15
VBUS_OTG: C64.1 C65.1 C66.1 P9.1(5VUSB) R95.2 U9.8(OUT_A)
VCC_RTC: C28.1 P1.B92(B) ; also on sheet 15
VDD33_BYP: C76.2 C77.2 C201.2 R44.1 R45.1 R47.1 R60.1 R61.1 R62.1 U5.26(VDD33_BYP1) U5.28(VDD_CORE_REG) U5.32(VDD33_BYP2)
ADC_IN0: P1.A50(A) P21.19
ADC_IN1: P1.A49(A) P21.21
ADC_IN2: P1.A48(A) P21.23
ADC_IN3: P1.A47(A) P21.25
ALT_BOOT#: P1.A2(A) P21.34 SW6.2 SW6.4
CAN0_GND: E12.1 P17.6 R7.1 U35.5(GND2) U38.2(GND)
CAN0_H: P17.3 R2004.1 U38.7(CANH)
CAN0_L: P17.4 R2004.2 U38.6(CANL)
CAN0_RX: P1.B105(B) U35.2(OUTA)
CAN0_STB_PD: R7.2 U38.8(STBY)
CAN0_TX: P1.B104(B) R13.2 U35.3(INB)
CAN0_VCC: E11.1 P17.1 U35.8(VCC2) U38.3(VCC)
CAN1_RX: P1.B107(B)
CAN1_TX: P1.B106(B)
CAN2_GND: E14.1 P18.6 R14.1 U39.5(GND2) U40.2(GND)
CAN2_H: P18.3 R2005.1 U40.7(CANH)
CAN2_L: P18.4 R2005.2 U40.6(CANL)
CAN2_RX: P1.B109(B) U39.2(OUTA)
CAN2_STB_PD: R14.2 U40.8(STBY)
CAN2_TX: P1.B108(B) R16.2 U39.3(INB)
CAN2_VCC: E13.1 P18.1 U39.8(VCC2) U40.3(VCC)
CARRIER_3V3_GPIO0_2: R144.2 U31.3(I/O0.2)
CARRIER_3V3_GPIO0_3: R264.2 U31.4(I/O0.3)
CARRIER_3V3_GPIO0_4: R265.2 U31.5(I/O0.4)
CARRIER_3V3_GPIO0_5: R176.1 U31.6(I/O0.5)
CARRIER_3V3_GPIO0_6: R177.2 U31.7(I/O0.6)
CARRIER_3V3_GPIO1_0: R204.2 U31.10(I/O1.0)
CARRIER_3V3_GPIO1_1: R200.2 U31.11(I/O1.1)
CARRIER_3V3_GPIO1_2: R199.2 U31.12(I/O1.2)
CARRIER_3V3_GPIO1_3: R205.2 U31.13(I/O1.3)
CARRIER_3V3_GPIO1_4: R209.2 U31.14(I/O1.4)
CARRIER_3V3_GPIO1_5: R206.2 U31.15(I/O1.5)
CARRIER_3V3_GPIO1_6: R207.2 U31.16(I/O1.6)
COLD_RESET_IN: P2.A40(A) P20.28 SW5.2 SW5.4
CSI1_B_FLASH: P47.29(FLASH) U42.1(B2)
CSI1_B_FLASH_GPIO: R265.1 U42.4(A2)
CSI1_B_TRG: P47.12(TRIGGER) U42.8(B1)
CSI1_B_TRG_GPIO: R264.1 U42.5(A1)
CSI1_GPIO_PWRDN: P47.6(PWDN) U41.8(B1)
CSI1_GPIO_RST#: P47.21(RESET) U41.1(B2)
CSI1_I2C0_EN: R143.2 U32.6(OE)
CSI1_I2C0_SCL: P47.7(I2C_SCL) U32.8(B1)
CSI1_I2C0_SDA: P47.8(I2C_SDA) U32.1(B2)
CSI1_PWRDN_RST_EN: R220.2 U41.6(OE)
CSI1_TRG_FLASH_EN: R221.2 U42.6(OE)
DBG_UART_RX: P1.A27(A) ; also on sheet 14
DBG_UART_TX: P1.A28(A) ; also on sheet 14
DEBUGSEL: R176.2 ; also on sheet 14
DSI0_DISP_RESET: R209.1 ; also on sheet 6
DSI0_INT_GPIO: R200.1 ; also on sheet 6
DSI0_LED_GPIO: R199.1 ; also on sheet 6
DSI0_TS_RESET: R205.1 ; also on sheet 6
EPHY0_LED_10_100: D1.1(ANODE1) P1.B32(B)
EPHY0_LED_1000: D1.2(ANODE2) P1.B27(B)
EPHY0_LED_ACT: P1.B26(B) P3.A12(LED1_A)
EPHY0_TRXN0: P1.B33(B) P3.A2(MDI0-)
EPHY0_TRXN1: P1.B36(B) P3.A4(MDI1-)
EPHY0_TRXN2: P1.B39(B) P3.A8(MDI2-)
EPHY0_TRXN3: P1.B29(B) P3.A10(MDI3-)
EPHY0_TRXP0: P1.B34(B) P3.A1(MDI0+)
EPHY0_TRXP1: P1.B37(B) P3.A3(MDI1+)
EPHY0_TRXP2: P1.B40(B) P3.A7(MDI2+)
EPHY0_TRXP3: P1.B30(B) P3.A9(MDI3+)
EPHY0_TXC_BYP: P1.B25(B) P20.1
EPHY1_LED_10_100: D2.1(ANODE1) P1.B5(B)
EPHY1_LED_1000: D2.2(ANODE2) P1.B7(B)
EPHY1_LED_ACT: P1.B6(B) P3.B12(LED1_A)
EPHY1_TRXN0: P1.B18(B) P3.B2(MDI0-)
EPHY1_TRXN1: P1.B15(B) P3.B4(MDI1-)
EPHY1_TRXN2: P1.B12(B) P3.B8(MDI2-)
EPHY1_TRXN3: P1.B10(B) P3.B10(MDI3-)
EPHY1_TRXP0: P1.B19(B) P3.B1(MDI0+)
EPHY1_TRXP1: P1.B16(B) P3.B3(MDI1+)
EPHY1_TRXP2: P1.B13(B) P3.B7(MDI2+)
EPHY1_TRXP3: P1.B9(B) P3.B9(MDI3+)
EPHY1_TXC_BYP: P1.B20(B) P20.3
ESAI0_FSR: P1.A81(A)
ESAI0_FST: P1.A79(A)
ESAI0_SCKR: P1.A78(A)
ESAI0_SCKT: P1.A77(A)
ESAI0_TX0: P1.A76(A)
ESAI0_TX1: P1.A75(A)
ESAI0_TX2_RX3: P1.A74(A)
ESAI0_TX3_RX2: P1.A73(A)
ESAI0_TX4_RX1: P1.A72(A)
ESAI0_TX5_RX0: P1.A71(A)
ETH0_MDC: P1.B3(B)
ETH0_MDIO: P1.B2(B)
ETH0_REFCLK: P1.B24(B) P21.3
ETH1_CT1: C19.1 C20.1 P3.A5(CT1)
ETH1_CT2: C23.1 P3.A6(CT2)
ETH1_GREEN_LED_CAT: P3.A11(LED1_C) R50.1
ETH1_MDC: P1.A17(A)
ETH1_MDIO: P1.A18(A)
ETH1_REFCLK: P1.B4(B) P21.1
ETH1_YELLOW_LED_AN: D1.3(CATHODE) P3.A14(LED2_A)
ETH1_YELLOW_LED_CAT: P3.A13(LED2_C) R51.1
ETH2_CT1: C21.1 C22.1 P3.B5(CT1)
ETH2_CT2: C24.1 P3.B6(CT2)
ETH2_GREEN_LED_CAT: P3.B11(LED1_C) R52.1
ETH2_YELLOW_LED_AN: D2.3(CATHODE) P3.B14(LED2_A)
ETH2_YELLOW_LED_CAT: P3.B13(LED2_C) R56.1
EXPANDER_A0: R166.1 R260.2 U31.18(A0)
EXPANDER_A1: R167.1 R259.2 U31.23(A1)
EXPANDER_A2: R136.1 R258.2 U31.24(A2)
FB_LDO_1V5: R106.1 R107.1 U12.6(ADJ)
FB_LDO_1V8: R97.1 R98.1 U10.6(ADJ)
FB_LDO_2V8: R102.1 R103.2 U11.6(ADJ)
GPIO_SATA_PCIe_SEL: P1.A12(A) ; also on sheet 5
GPIO_USB_HUB_CONNECT: P1.B46(B) R161.1
GPIO_USB_HUB_RESETn: P1.B47(B) R55.1
HDMI_RX_ARC_P: P2.B84(B) ; also on sheet 1
HDMI_RX_CEC: P2.B86(B) ; also on sheet 1
HDMI_RX_CLK_N: P2.B82(B) ; also on sheet 1
HDMI_RX_CLK_P: P2.B81(B) ; also on sheet 1
HDMI_RX_DAT0_N: P2.B79(B) ; also on sheet 1
HDMI_RX_DAT0_P: P2.B78(B) ; also on sheet 1
HDMI_RX_DAT1_N: P2.B76(B) ; also on sheet 1
HDMI_RX_DAT1_P: P2.B75(B) ; also on sheet 1
HDMI_RX_DAT2_N: P2.B69(B) ; also on sheet 1
HDMI_RX_DAT2_P: P2.B68(B) ; also on sheet 1
HDMI_RX_DDC_SCL: P2.B71(B) ; also on sheet 1
HDMI_RX_DDC_SDA: P2.B72(B) ; also on sheet 1
HDMI_RX_HPD: P2.B73(B) ; also on sheet 1
HDMI_RX_MON_5V: P2.B85(B) ; also on sheet 1
HDMI_TX_AUX_N: P2.B104(B) ; also on sheet 4
HDMI_TX_AUX_P: P2.B105(B) ; also on sheet 4
HDMI_TX_CEC: P2.B93(B) ; also on sheet 4
HDMI_TX_CLK_DP3_N: P2.B102(B) ; also on sheet 4
HDMI_TX_CLK_DP3_P: P2.B101(B) ; also on sheet 4
HDMI_TX_DAT0_DP2_N: P2.B99(B) ; also on sheet 4
HDMI_TX_DAT0_DP2_P: P2.B98(B) ; also on sheet 4
HDMI_TX_DAT1_DP1_N: P2.B96(B) ; also on sheet 4
HDMI_TX_DAT1_DP1_P: P2.B95(B) ; also on sheet 4
HDMI_TX_DAT2_DP0_N: P2.B89(B) ; also on sheet 4
HDMI_TX_DAT2_DP0_P: P2.B88(B) ; also on sheet 4
HDMI_TX_DDC_SCL: P2.B92(B) ; also on sheet 4
HDMI_TX_DDC_SDA: P2.B91(B) ; also on sheet 4
HDMI_TX_HPD: P2.B107(B) ; also on sheet 4
HUB_CONNECT: R24.2 R60.2 R161.2 U5.2(HUB_CONNECT)
HUB_INT_N: R17.2 R44.2 U5.5(INT_N)
HUB_OCS_N: R61.2 U5.1(OCS_N)
HUB_PRTPWR: R62.2 U5.4(PRTPWR)
HUB_RBIAS: R157.1 U5.30(RBIAS)
HUB_REFCLK: OSC2.3(OUT) U5.29(REFCLK)
HUB_RESETn: R55.2 R168.1 U5.12(RESET_N)
HUB_SEL0: R18.2 R47.2 U5.10(REF_SEL0)
HUB_SEL1: R19.2 R45.2 U5.9(REF_SEL1)
HUB_VBAT: C30.1 R38.2 R165.1 U5.25(VBAT)
HUB_VDD12: C29.1 U5.6(VDD12_BYP1) U5.11(VDD12_BYP2) U5.13(VDD12_BYP3)
I2C1_3V3_SCL: P1.A15(A) P20.6
I2C1_3V3_SDA: P1.A16(A) P20.8
JTAG_HDR_10: P29.9 R162.2
JTAG_nRST: P2.B2(B) P29.10 R155.2
JTAG_TCK: P1.A9(A) P29.4 R156.1
JTAG_TDI: P1.A7(A) P29.8 R153.2
JTAG_TDO: P1.A8(A) P29.6
JTAG_TMS: P1.A10(A) P29.2 R110.2
JTAG_VCC: P29.1 R110.1 R138.1 R152.1 R153.1 R155.1
LVDS0_BL_PWM: P2.A25(A) ; also on sheet 3
LVDS0_CH0_CLK_N: P2.B15(B) ; also on sheet 3
LVDS0_CH0_CLK_P: P2.B16(B) ; also on sheet 3
LVDS0_CH0_TX0_N: P2.B12(B) ; also on sheet 3
LVDS0_CH0_TX0_P: P2.B13(B) ; also on sheet 3
LVDS0_CH0_TX1_N: P2.B9(B) ; also on sheet 3
LVDS0_CH0_TX1_P: P2.B10(B) ; also on sheet 3
LVDS0_CH0_TX2_N: P2.B6(B) ; also on sheet 3
LVDS0_CH0_TX2_P: P2.B7(B) ; also on sheet 3
LVDS0_CH0_TX3_N: P2.B3(B) ; also on sheet 3
LVDS0_CH0_TX3_P: P2.B4(B) ; also on sheet 3
LVDS0_CH1_CLK_N: P2.A30(A) ; also on sheet 3
LVDS0_CH1_CLK_P: P2.A29(A) ; also on sheet 3
LVDS0_CH1_TX0_N: P2.A33(A) ; also on sheet 3
LVDS0_CH1_TX0_P: P2.A32(A) ; also on sheet 3
LVDS0_CH1_TX1_N: P2.A36(A) ; also on sheet 3
LVDS0_CH1_TX1_P: P2.A35(A) ; also on sheet 3
LVDS0_CH1_TX2_N: P2.A39(A) ; also on sheet 3
LVDS0_CH1_TX2_P: P2.A38(A) ; also on sheet 3
LVDS0_CH1_TX3_N: P2.A43(A) ; also on sheet 3
LVDS0_CH1_TX3_P: P2.A42(A) ; also on sheet 3
LVDS0_GPIO02: P2.A44(A)
LVDS0_INT_GPIO: R204.1 ; also on sheet 3
LVDS0_LED_GPIO: R207.1 ; also on sheet 3
LVDS0_TS_INT: P2.A24(A) ; also on sheet 3
LVDS0_TS_RESET: R206.1 ; also on sheet 3
LVDS0_TS_SCL: P2.A26(A) ; also on sheet 3
LVDS0_TS_SDA: P2.A27(A) ; also on sheet 3
LVDS1_BL_PWM: P2.B61(B)
LVDS1_CH0_CLK_N: P2.B32(B)
LVDS1_CH0_CLK_P: P2.B33(B)
LVDS1_CH0_TX0_N: P2.B29(B)
LVDS1_CH0_TX0_P: P2.B30(B)
LVDS1_CH0_TX1_N: P2.B26(B)
LVDS1_CH0_TX1_P: P2.B27(B)
LVDS1_CH0_TX2_N: P2.B23(B)
LVDS1_CH0_TX2_P: P2.B24(B)
LVDS1_CH0_TX3_N: P2.B18(B)
LVDS1_CH0_TX3_P: P2.B19(B)
LVDS1_CH1_CLK_N: P2.B35(B)
LVDS1_CH1_CLK_P: P2.B36(B)
LVDS1_CH1_TX0_N: P2.B38(B)
LVDS1_CH1_TX0_P: P2.B39(B)
LVDS1_CH1_TX1_N: P2.B43(B)
LVDS1_CH1_TX1_P: P2.B44(B)
LVDS1_CH1_TX2_N: P2.B46(B)
LVDS1_CH1_TX2_P: P2.B47(B)
LVDS1_CH1_TX3_N: P2.B49(B)
LVDS1_CH1_TX3_P: P2.B50(B)
LVDS1_GPIO02: P2.B22(B)
LVDS1_TS_INT: P2.B20(B)
LVDS1_TS_SCL: P2.B42(B)
LVDS1_TS_SDA: P2.B40(B)
M40_UART0_RX: P1.A25(A) ; also on sheet 14
M40_UART0_TX: P1.A24(A) ; also on sheet 14
M41_UART0_RX: P1.A23(A) ; also on sheet 14
M41_UART0_TX: P1.A22(A) ; also on sheet 14
MCLK_IN0: P1.A83(A)
MCLK_OUT0: P1.A82(A) ; also on sheet 2
MIPI_CSI0_CLK_N: P2.A78(A) P25.3
MIPI_CSI0_CLK_P: P2.A79(A) P25.1
MIPI_CSI0_DATA0_N: P2.A75(A) P25.9
MIPI_CSI0_DATA0_P: P2.A76(A) P25.7
MIPI_CSI0_DATA1_N: P2.A81(A) P25.15
MIPI_CSI0_DATA1_P: P2.A82(A) P25.13
MIPI_CSI0_DATA2_N: P2.A72(A) P25.4
MIPI_CSI0_DATA2_P: P2.A73(A) P25.2
MIPI_CSI0_DATA3_N: P2.A84(A) P25.10
MIPI_CSI0_DATA3_P: P2.A85(A) P25.8
MIPI_CSI0_GPIO_PWRDN: P2.A71(A) P25.20
MIPI_CSI0_GPIO_RST#: P2.A69(A) P25.18
MIPI_CSI0_I2C0_SCL: P2.A91(A) P25.14
MIPI_CSI0_I2C0_SDA: P2.A92(A) P25.16
MIPI_CSI0_MCLK_OUT: P2.A87(A) P25.19
MIPI_CSI1_CLK_N: P2.A102(A) P47.24(MIPI_CLK_N)
MIPI_CSI1_CLK_P: P2.A101(A) P47.25(MIPI_CLK_P)
MIPI_CSI1_DATA0_N: P2.A99(A) P47.19(MIPI_D0_N)
MIPI_CSI1_DATA0_P: P2.A98(A) P47.20(MIPI_D0_P)
MIPI_CSI1_DATA1_N: P2.A106(A) P47.15(MIPI_D1_N)
MIPI_CSI1_DATA1_P: P2.A105(A) P47.16(MIPI_D1_P)
MIPI_CSI1_DATA2_N: P2.A89(A) P47.10(MIPI_D2_N)
MIPI_CSI1_DATA2_P: P2.A88(A) P47.11(MIPI_D2_P)
MIPI_CSI1_DATA3_N: P2.A109(A) P47.27(MIPI_D3_N)
MIPI_CSI1_DATA3_P: P2.A108(A) P47.28(MIPI_D3_P)
MIPI_CSI1_GPIO_PWRDN: P2.A104(A) U41.5(A1)
MIPI_CSI1_GPIO_RST#: P2.A96(A) U41.4(A2)
MIPI_CSI1_I2C0_SCL: P2.A94(A) U32.5(A1)
MIPI_CSI1_I2C0_SDA: P2.A95(A) U32.4(A2)
MIPI_CSI1_MCLK_OUT: P2.A93(A)
MIPI_DSI0_CLK_N: P2.B58(B) ; also on sheet 6
MIPI_DSI0_CLK_P: P2.B59(B) ; also on sheet 6
MIPI_DSI0_DATA0_N: P2.B55(B) ; also on sheet 6
MIPI_DSI0_DATA0_P: P2.B56(B) ; also on sheet 6
MIPI_DSI0_DATA1_N: P2.B62(B) ; also on sheet 6
MIPI_DSI0_DATA1_P: P2.B63(B) ; also on sheet 6
MIPI_DSI0_DATA2_N: P2.B52(B) ; also on sheet 6
MIPI_DSI0_DATA2_P: P2.B53(B) ; also on sheet 6
MIPI_DSI0_DATA3_N: P2.B65(B) ; also on sheet 6
MIPI_DSI0_DATA3_P: P2.B66(B) ; also on sheet 6
MIPI_DSI0_I2C_SCL: P2.A66(A) ; also on sheet 6
MIPI_DSI0_I2C_SDA: P2.A65(A) ; also on sheet 6
MIPI_DSI0_INT: P2.A68(A) ; also on sheet 6
MIPI_DSI0_PWM: P2.A67(A) ; also on sheet 6
MIPI_DSI1_CLK_N: P2.A53(A)
MIPI_DSI1_CLK_P: P2.A52(A)
MIPI_DSI1_DATA0_N: P2.A50(A)
MIPI_DSI1_DATA0_P: P2.A49(A)
MIPI_DSI1_DATA1_N: P2.A56(A)
MIPI_DSI1_DATA1_P: P2.A55(A)
MIPI_DSI1_DATA2_N: P2.A47(A)
MIPI_DSI1_DATA2_P: P2.A46(A)
MIPI_DSI1_DATA3_N: P2.A59(A)
MIPI_DSI1_DATA3_P: P2.A58(A)
MIPI_DSI1_I2C_SCL: P2.A61(A)
MIPI_DSI1_I2C_SDA: P2.A62(A)
MIPI_DSI1_INT: P2.A63(A)
MIPI_DSI1_PWM: P2.A64(A)
mPCIE_CLK_REQn: P1.B72(B) ; also on sheet 5
mPCIE_REF_CLKN: P1.B75(B) ; also on sheet 5
mPCIE_REF_CLKP: P1.B76(B) ; also on sheet 5
mPCIE_RSTn: P1.B71(B) ; also on sheet 5
mPCIE_RXN: P1.B65(B) ; also on sheet 5
mPCIE_RXP: P1.B66(B) ; also on sheet 5
mPCIE_TXN: P1.B68(B) ; also on sheet 5
mPCIE_TXP: P1.B69(B) ; also on sheet 5
mPCIe_USB_DN: P1.B43(B) ; also on sheet 5
mPCIe_USB_DP: P1.B42(B) ; also on sheet 5
mPCIE_WAKEn: P1.B73(B) ; also on sheet 5
OSC2_EN: OSC2.1(EN) R11.2 R12.1 R15.1
OSC2_VCC: C78.1 OSC2.4(VCC) R141.2 R158.2
OTG_DN: L6.2 P9.2(D-)
OTG_DP: L6.1 P9.3(D+)
PCIE0_MUX_SEL: E15.2 P1.B81(B) R144.1
PCIE0_MUX_SEL_J: E15.1 R54.1
PCIE1_CLKGEN1_N: P1.B88(B) ; also on sheet 5
PCIE1_CLKGEN1_P: P1.B89(B) ; also on sheet 5
PCIE1_CLKREQ#: P1.B91(B) ; also on sheet 5
PCIE1_PERST#: P1.B83(B) ; also on sheet 5
PCIE1_RX0_N: P1.B85(B) ; also on sheet 5
PCIE1_RX0_P: P1.B86(B) ; also on sheet 5
PCIE1_TX0_N: P1.B78(B) ; also on sheet 5
PCIE1_TX0_P: P1.B79(B) ; also on sheet 5
PCIE1_WAKE#: P1.B82(B) ; also on sheet 5
PCIE_SATA_CLKGEN0_N: P1.B95(B) ; also on sheet 5
PCIE_SATA_CLKGEN0_P: P1.B96(B) ; also on sheet 5
PCIE_SATA_CLKREQ#: P1.B93(B) ; also on sheet 5
PCIE_SATA_RX0_N: P1.B98(B) ; also on sheet 5
PCIE_SATA_RX0_P: P1.B99(B) ; also on sheet 5
PCIE_SATA_TX0_N: P1.B101(B) ; also on sheet 5
PCIE_SATA_TX0_P: P1.B102(B) ; also on sheet 5
PMIC_ON_REQ: P2.B108(B) P20.4 R150.1 U10.4(EN) ; also on sheet 15
POR_B_1V8: P1.B61(B) P20.30 R168.2 ; also on sheet 3 6
PWM3 or GPIO_AW53: P1.A104(A)
PWRBTN: P2.A20(A) P20.31 SW4.2 SW4.4
RS485_CTRL: R177.1 ; also on sheet 14
RTCK: P29.7 R43.2
RXD0_OUTB: U35.6(OUTB) U38.1(TXD)
RXD2_OUTB: U39.6(OUTB) U40.1(TXD)
SAI1_RXC: P1.A89(A)
SAI1_RXD: P1.A88(A) ; also on sheet 2
SAI1_RXFS: P1.A87(A) ; also on sheet 2
SAI1_TXC: P1.A86(A) ; also on sheet 2
SAI1_TXD: P1.A85(A) ; also on sheet 2
SAI1_TXFS: P1.A84(A) ; also on sheet 2
SAI2_RXC: P1.A103(A)
SAI2_RXD: P1.A102(A)
SAI2_RXFS: P1.A101(A)
SCU_UART0_RX: P1.A5(A) P20.11 ; also on sheet 14
SCU_UART0_TX: P1.A6(A) P20.9 ; also on sheet 14
SPDIF_EXT_CLK: P1.A93(A)
SPDIF_RX: P1.A92(A) ; also on sheet 2
SPDIF_TX: P1.A91(A) ; also on sheet 2
SPI0_CS0: P1.A96(A) P20.14
SPI0_CS1: P1.A95(A) P20.16
SPI0_MISO: P1.A97(A) P20.20
SPI0_MOSI: P1.A98(A) P20.22
SPI0_SCK: P1.A99(A) P20.18
SPI2_CS0: P1.A66(A) P21.22
SPI2_CS1: P1.A65(A) P21.24
SPI2_MISO: P1.A67(A) P21.28
SPI2_MOSI: P1.A68(A) P21.30
SPI2_SCK: P1.A69(A) P21.26
SPI3_CS0: P1.A106(A) P20.21
SPI3_CS1: P1.A105(A) P20.23
SPI3_MISO: P1.A107(A) P20.27
SPI3_MOSI: P1.A108(A) P20.29
SPI3_SCK: P1.A109(A) P20.25
SW_3V3_ON: P2.B109(B) ; also on sheet 15
SYS_I2C_SCL: P1.A13(A) R74.2 U5.8(SCL) U31.19(SCL) ; also on sheet 2 5 14
SYS_I2C_SDA: P1.A14(A) R76.2 U5.7(SDA) U31.20(SDA) ; also on sheet 2 5 14
TAMPER_IN: P2.A22(A) P21.9
TAMPER_OUT: P2.A23(A) P21.11
TXD0_INA: U35.7(INA) U38.4(RXD)
TXD2_INA: U39.7(INA) U40.4(RXD)
UART1_CTS: P1.A32(A) P20.17
UART1_RTS: P1.A33(A) P20.19
UART1_RX: P1.A34(A) P20.15
UART1_TX: P1.A35(A) P20.13
UART2_RX: P1.A29(A) ; also on sheet 14
UART2_TX: P1.A30(A) ; also on sheet 14
UART3_RX: P1.A19(A) P20.12
UART3_TX: P1.A20(A) P20.10
USB1_VBUS_EN: Q4.3(D) R91.2 R145.1 U9.1(EN_A)
USB_2_DN: L14.2 U30.2(D-)
USB_2_DP: L14.1 U30.3(D+)
USB_3_DN: L15.2 U30.6(D-)
USB_3_DP: L15.1 U30.7(D+)
USB_HSIC0_DATA: P1.B63(B) U5.15(DATA)
USB_HSIC0_STROBE: P1.B62(B) U5.16(STROBE)
USB_HUB1_DN: U5.24(USBDN1_DP) ; also on sheet 5
USB_HUB1_DP: U5.23(USBDN1_DM) ; also on sheet 5
USB_HUB2_DN: L14.3 U5.21(USBDN2_DM)
USB_HUB2_DP: L14.4 U5.22(USBDN2_DP)
USB_HUB3_DN: L15.3 U5.19(USBDN3_DM)
USB_HUB3_DP: L15.4 U5.20(USBDN3_DP)
USB_ID_CONN: P9.4(ID) Q4.1(G) R92.1 R94.1
USB_OTG1_ID: P1.B45(B)
USB_OTG1_VBUS_DET: P1.A3(A) R149.2
USB_OTG2_DN: L6.3 P1.B53(B)
USB_OTG2_DP: L6.4 P1.B52(B)
USB_OTG2_ID: P1.B48(B) R94.2
USB_OTG2_OC: P1.B50(B) R128.2 U9.2(FLG_A)
USB_OTG2_PWREN: P1.B49(B) R145.2
USB_OTG2_VBUS_DET: P1.A4(A) R95.1 R149.1
USB_SS3_RX_N: L8.3 P1.B56(B)
USB_SS3_RX_P: L8.4 P1.B55(B)
USB_SS3_TX_N: L7.3 P1.B59(B)
USB_SS3_TX_P: L7.4 P1.B58(B)
USB_VCC3: F5.1 U30.1(VBUS)
USB_VCC4: F6.1 U30.5(VBUS)
USBSS_RXN_CON: L8.2 P9.9(RX-)
USBSS_RXP_CON: L8.1 P9.10(RX+)
USBSS_TXN_CON: L7.2 P9.6(TX-)
USBSS_TXP_CON: L7.1 P9.7(TX+)
USDHC1_CD_B: P1.A52(A) ; also on sheet 14
USDHC1_CLK: P1.A63(A) ; also on sheet 14
USDHC1_CMD: P1.A62(A) ; also on sheet 14
USDHC1_DATA0: P1.A59(A) ; also on sheet 14
USDHC1_DATA1: P1.A58(A) ; also on sheet 14
USDHC1_DATA2: P1.A57(A) ; also on sheet 14
USDHC1_DATA3: P1.A56(A) ; also on sheet 14
USDHC1_DATA4: P1.A55(A)
USDHC1_DATA5: P1.A54(A)
USDHC1_RESET_B: P1.A64(A)
USDHC1_STROBE: P1.A61(A)
USDHC1_WP: P1.A53(A) ; also on sheet 14
USDHC2_CD_B: P1.A44(A) ; also on sheet 14
USDHC2_CLK: P1.A43(A) ; also on sheet 14
USDHC2_CMD: P1.A42(A) ; also on sheet 14
USDHC2_DATA0: P1.A39(A) ; also on sheet 14
USDHC2_DATA1: P1.A38(A) ; also on sheet 14
USDHC2_DATA2: P1.A37(A) ; also on sheet 14
USDHC2_DATA3: P1.A36(A) ; also on sheet 14
USDHC2_RESET_B: P1.A40(A) P20.5 ; also on sheet 14
USDHC2_WP: P1.A45(A) ; also on sheet 14
V_SOM: C67.1 C69.1 C71.1 C222.1 C403.1 C404.1 C405.1 C406.1 C407.1 C408.1 C409.2 C410.2 C411.2 P2.A2(A) P2.A3(A) P2.A4(A) P2.A5(A) P2.A6(A) P2.A7(A) P2.A8(A) P2.A9(A) P2.A10(A) P2.A12(A) P2.A13(A) P2.A14(A) P2.A15(A) P2.A16(A) P2.A17(A) P2.A18(A) R100.2 R105.2 R150.2 U10.1(Vin1) U10.2(Vin2) U11.1(Vin1) U11.2(Vin2) U12.1(Vin1) U12.2(Vin2) ; also on sheet 3 6 15
V_SOM_EN: P21.5 ; also on sheet 15
VIO_CAMERA: C154.1 C156.1 C158.1 R143.1 R220.1 R221.1 R305.1 R306.2 U32.7(VCCB) U41.7(VCCB) U42.7(VCCB)
VSB_1V5: C72.1 C219.1 C221.1 R106.2 U12.7(Vout1) U12.8(Vout2) ; also on sheet 5
VSB_1V5_EN: R104.2 R105.1 U12.4(EN)
VSB_1V8: C59.2 C68.1 C153.1 C155.1 C218.1 P21.18 P47.3(VCC_1P8) R93.1 R97.2 R138.2 R306.1 U10.7(Vout1) U10.8(Vout2) U32.3(VCCA) U41.3(VCCA) ; also on sheet 3 6 14
VSB_1V8_PGOOD: R93.2 R99.2 U10.3(PGOOD)
VSB_2V8: C70.1 P21.15 R101.1 R102.2 U11.7(Vout1) U11.8(Vout2)
VSB_2V8_EN: R99.1 R100.1 U11.4(EN)
VSB_2V8_PGOOD: R101.2 R104.1 U11.3(PGOOD)

Not connected (* = marked no-connect by the designer): P20 2* 7* 24* 26* 32* 34*; P21 2* 4* 8* 10* 13* 14* 16* 17* 20* 27* 29* 31* 32*; P47 13(RSVD1)* 23(RSVD2)* 30(RSVD3)*; U5 3(NC1)* 14(NC2)* 17(NC3)* 18(NC4)* 27(NC5)* 31(NC6)*; U9 3(FLG_B)* 4(EN_B)* 5(OUT_B)*; U12 3(PGOOD)*; U31 1(I/O0.0)* 2(I/O0.1)* 8(I/O0.7)* 17(I/O1.7)* 22(\\~{IN}T)*

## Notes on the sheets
sheet 9
- CARRIER BOARD INTERFACE
- SEQUENCE 2 ON
- Place 100nF ac coupling on BB near HDMI conn
- Place 100nF ac coupling on BB near HDMI conn
- Place 100nF ac coupling on BB near HDMI conn
- Place 100nF ac coupling on BB near HDMI conn
- 2K PU to 5V on BB for HDMI
  conn or 2K PD for DP
- Place 100nF ac coupling on BB near HDMI conn
- Connect to VCC 5V on BB
- 3.3V
- 1.8V
- 3.3V/2.5V/1.8V must be
  supplied by base for external
  PHY usage or for using the
  ENET interface as GPIO
- PLANE STITCHING
- CAPACITORS
sheet 10
- ETHERNET 0
- ETHERNET 1
- 100 Ohm
- 100 Ohm
- 100 Ohm
- 100 Ohm
- 100 Ohm
- 100 Ohm
- 100 Ohm
- 100 Ohm
- Layout notes
  1: 100ohm differential impedance control.
  2: Match each differential signals pair ± 5 mils.
  3: Not more than two vias on each differential trace
  4: GND stitching VIA near every signal VIA
  5: The spacing between differential pair signals and other signals should be at least three times the trace width.
sheet 11
- USB OTG
- DNP
- >2.4
- Micro USB 3 AB, 10pin
- USB 2.0 DUAL CONN
- 90 ohm
- 90 ohm
- I2C ADDRESS: 0X08
- USB 2.0 HUB
- DNP
- DNP
- DNP
- REFCLK VIH = 1.4V
- DNP
- DNP
- DNP
- DNP
- DNP
- DNP
- DNP
- DNP
sheet 12
- POWER/RESET/BOOT SWITCHES & JTAG
- JTAG HEADER
- DNP
- TMS
- JTAG_VTREF
- TCK
- GND
- TDI
- TDO
- GND
- nRST
- DNP
- 100mil CONN 1
- 100mil CONN 2
- Signals can be swaped freely
- Signals can be swaped freely
  except jumper dependent alt_boot
- SILK
- alt_boot jumper
- alt boot - connect P21-33 with P21-34
- Layout notes for PCIe and LVDS signals
  1: 100ohm differential impedance control for LVDS, 85ohm for PCIe.
  2: Match each differential signals pair ± 5 mils.
  3: Not more than two vias on each differential trace
  4: GND stitching VIA near every signal VIA
  5: The spacing between differential pair signal and other signals should at least three times the trace width.
sheet 13
- 30 pin Connector for e-CAM130_iMX8M
  (e-con System)
- MIPI-CSI MODULE
- DNP
- 1.8V
- 1.8V
- 3.3V
- 1.8V
- 1.8V
- 3.3V
- MIPI-CSI HEADER
- CAN
- CAN0 TRANSCEIVER
- 1.8V
- 1.8V
- 1.8V
- 1.8V
- 1.8V
- SILK
- CAN0 VCC jumper
- SILK
- VSB_1V5, VSB_1V8 & VCC_2V8 CSI sources
- CAN0 GND jumper
- CAN2 TRANSCEIVER
- Vout=Vfb*(1+Rt/Rb)=0.8*(1+13.3/10)=1.86V
- DNP
- SILK
- CAN2 VCC jumper
- SILK
- Vout=Vfb*(1+Rt/Rb)=0.8*(1+16.5/6.49)=2.8V
- CAN2 GND jumper
- GPIO EXPANDER
- DNP
- SILK
- I2C address: 0x20
- DNP
- Force PCIe to mPCIe
- Vout=Vfb*(1+Rt/Rb)=0.8*(1+9.1/10)=1.528V
- Layout notes
  1: 100ohm differential impedance control for CSI, 85 for PCIe, 90 for USB.
  2: Match each differential signals pair ± 5 mils and 40 mils for usb
  3: Not more than two vias on each differential trace
  4: GND stitching VIA near every signal VIA
  5: The spacing between differential pair signal and other signals should at least three times the trace width.
